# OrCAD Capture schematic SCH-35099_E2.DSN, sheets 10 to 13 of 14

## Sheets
10 10 Pheriperals: size C
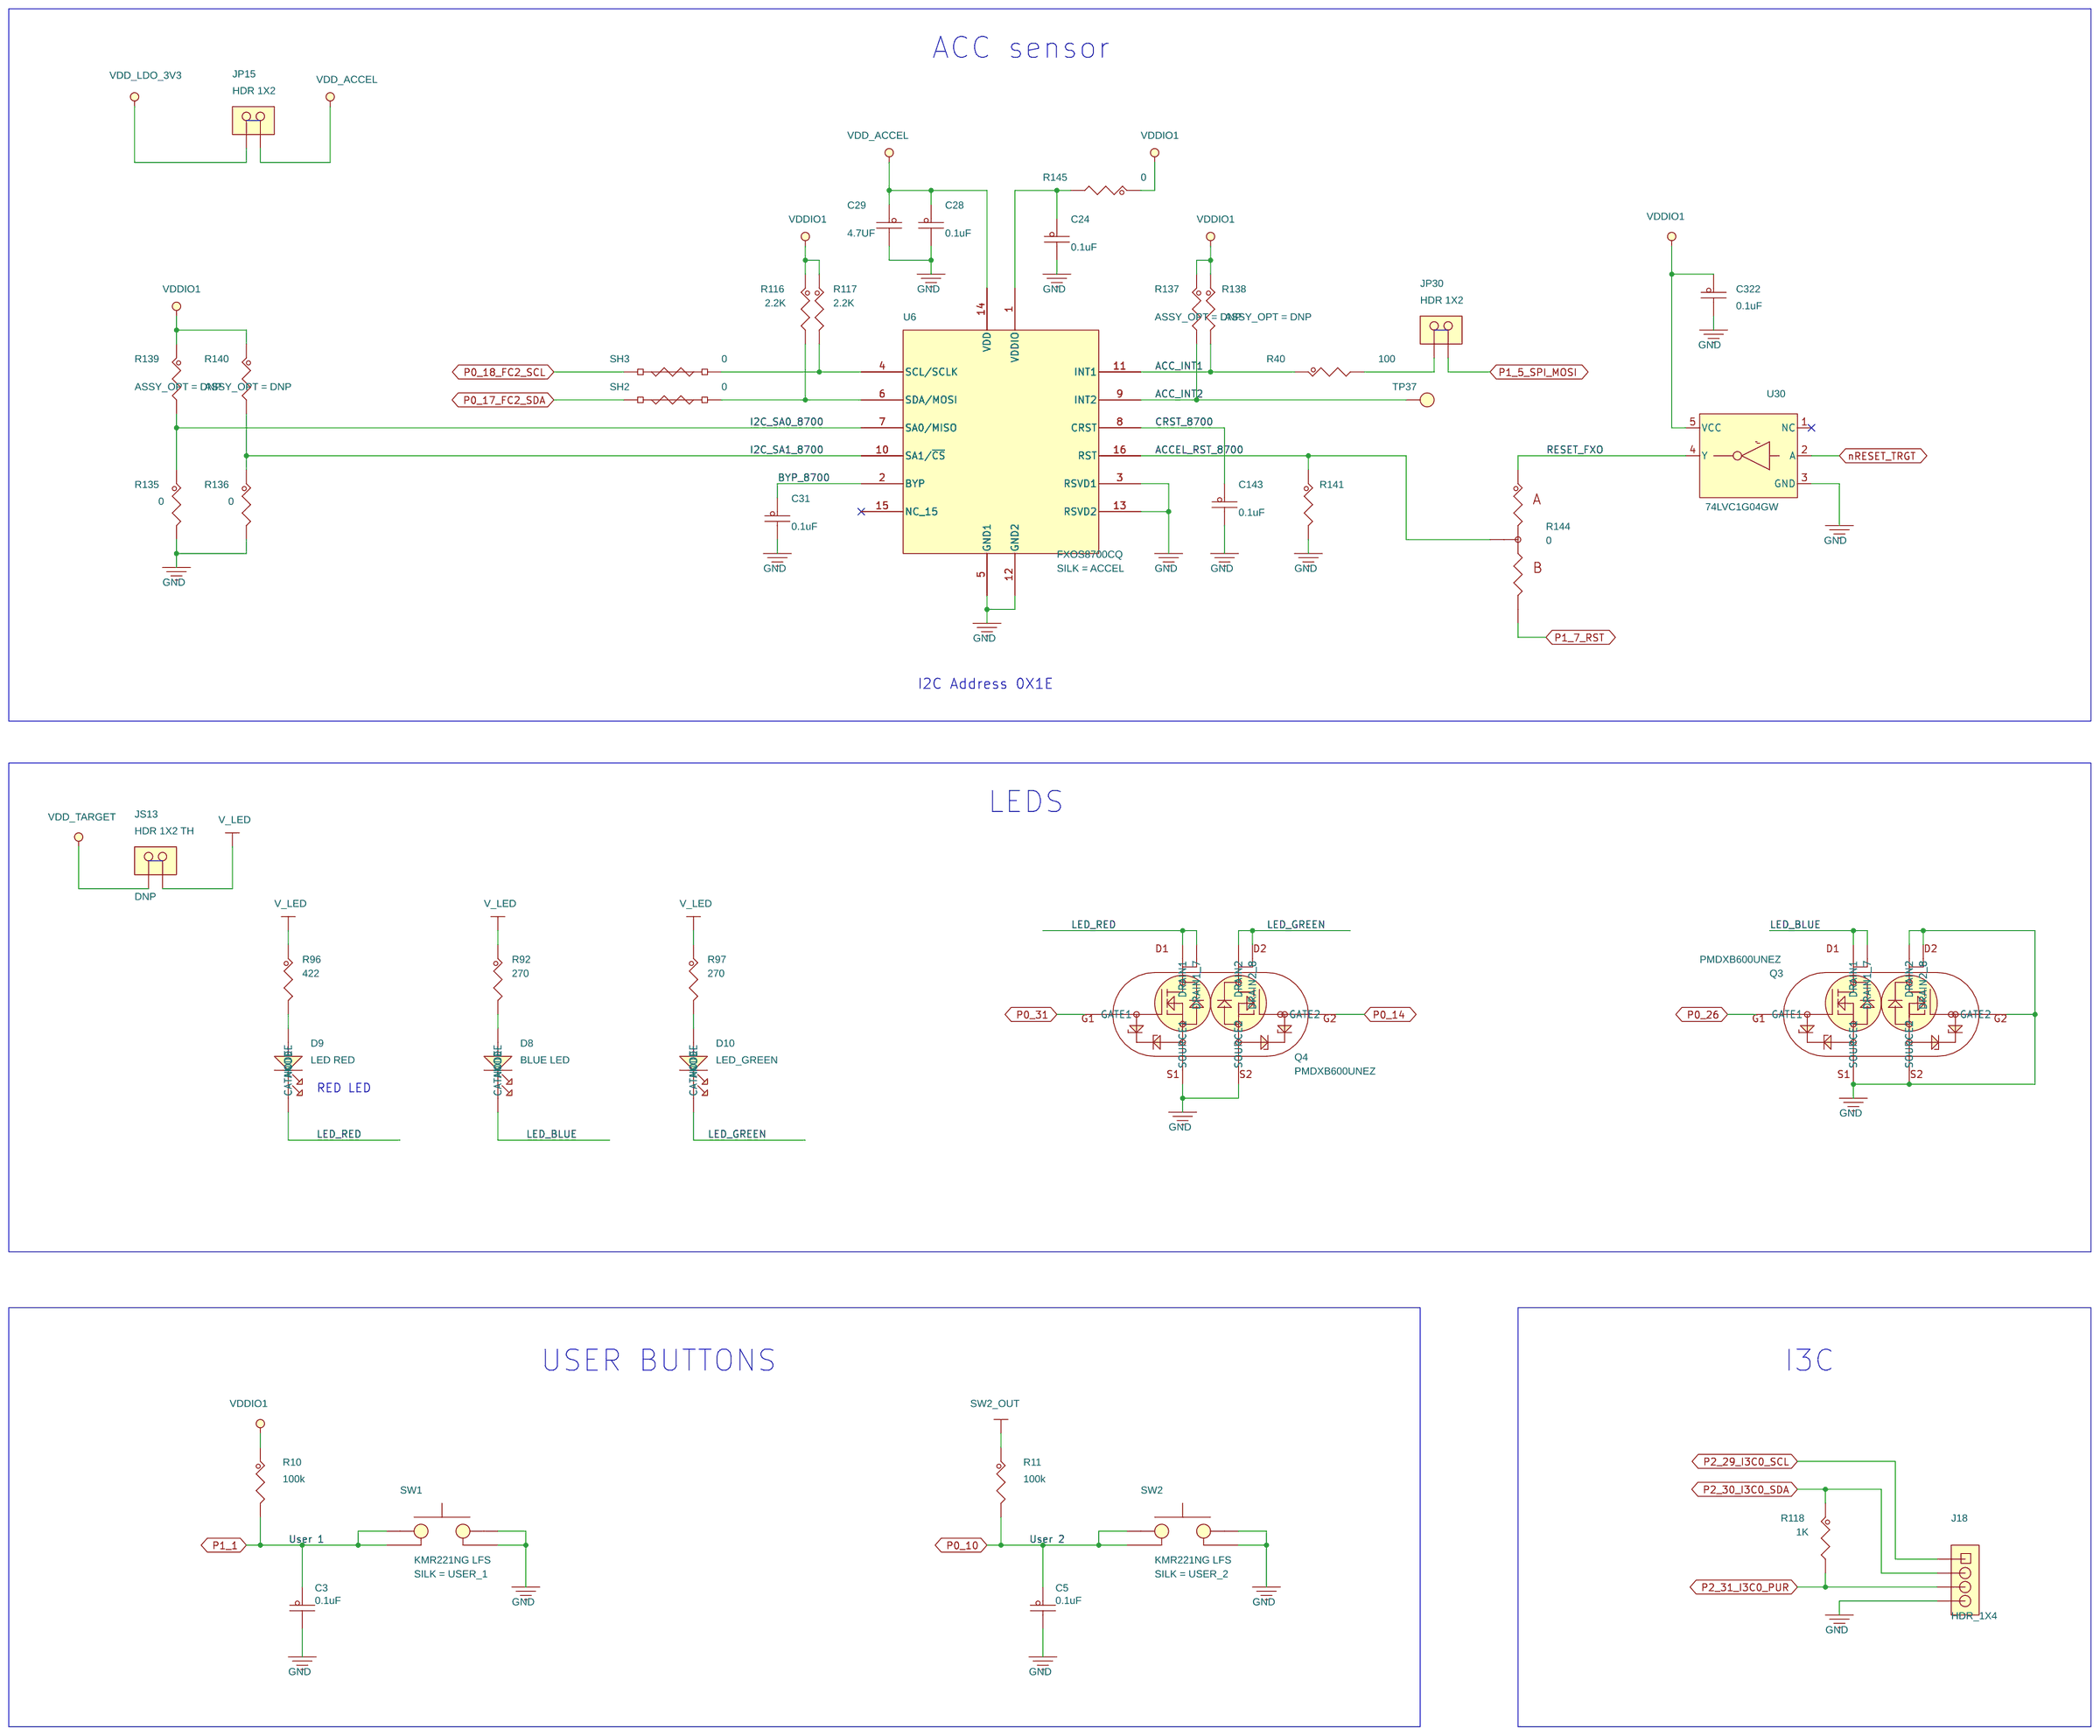
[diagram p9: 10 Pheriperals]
11 13 Debug Translator: size C
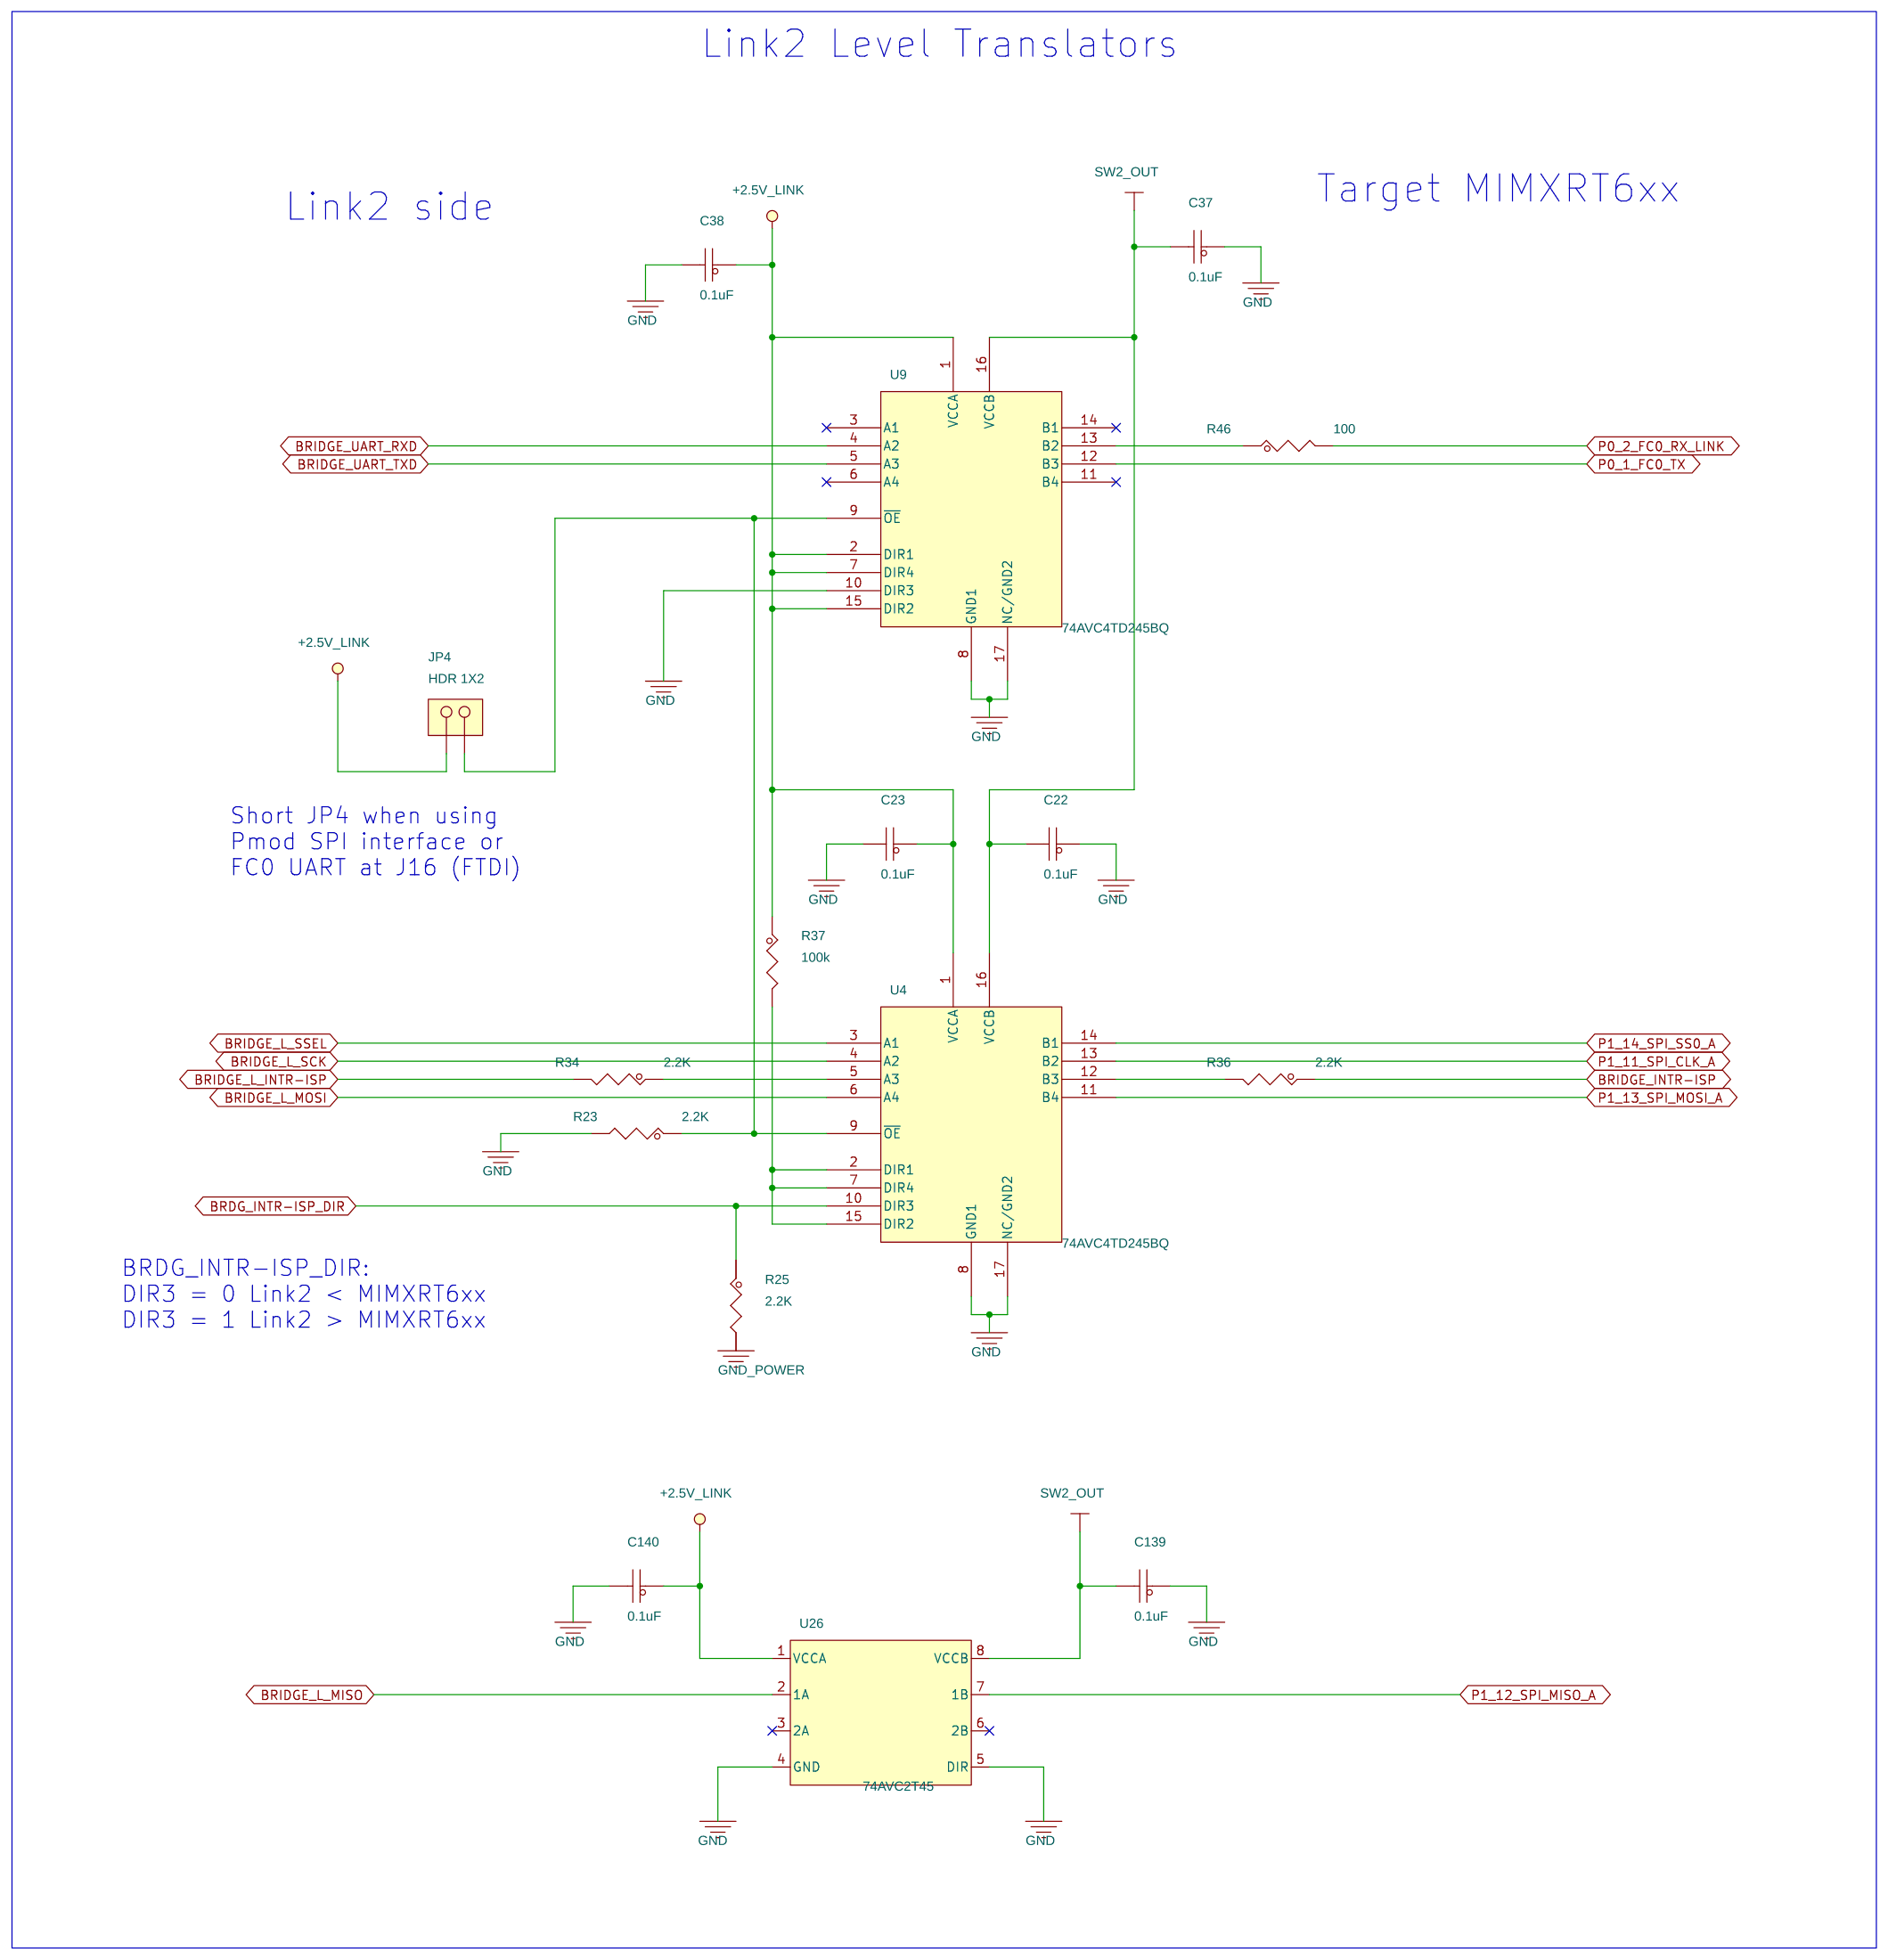
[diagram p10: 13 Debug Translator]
12 14 Link2 Debug: size C
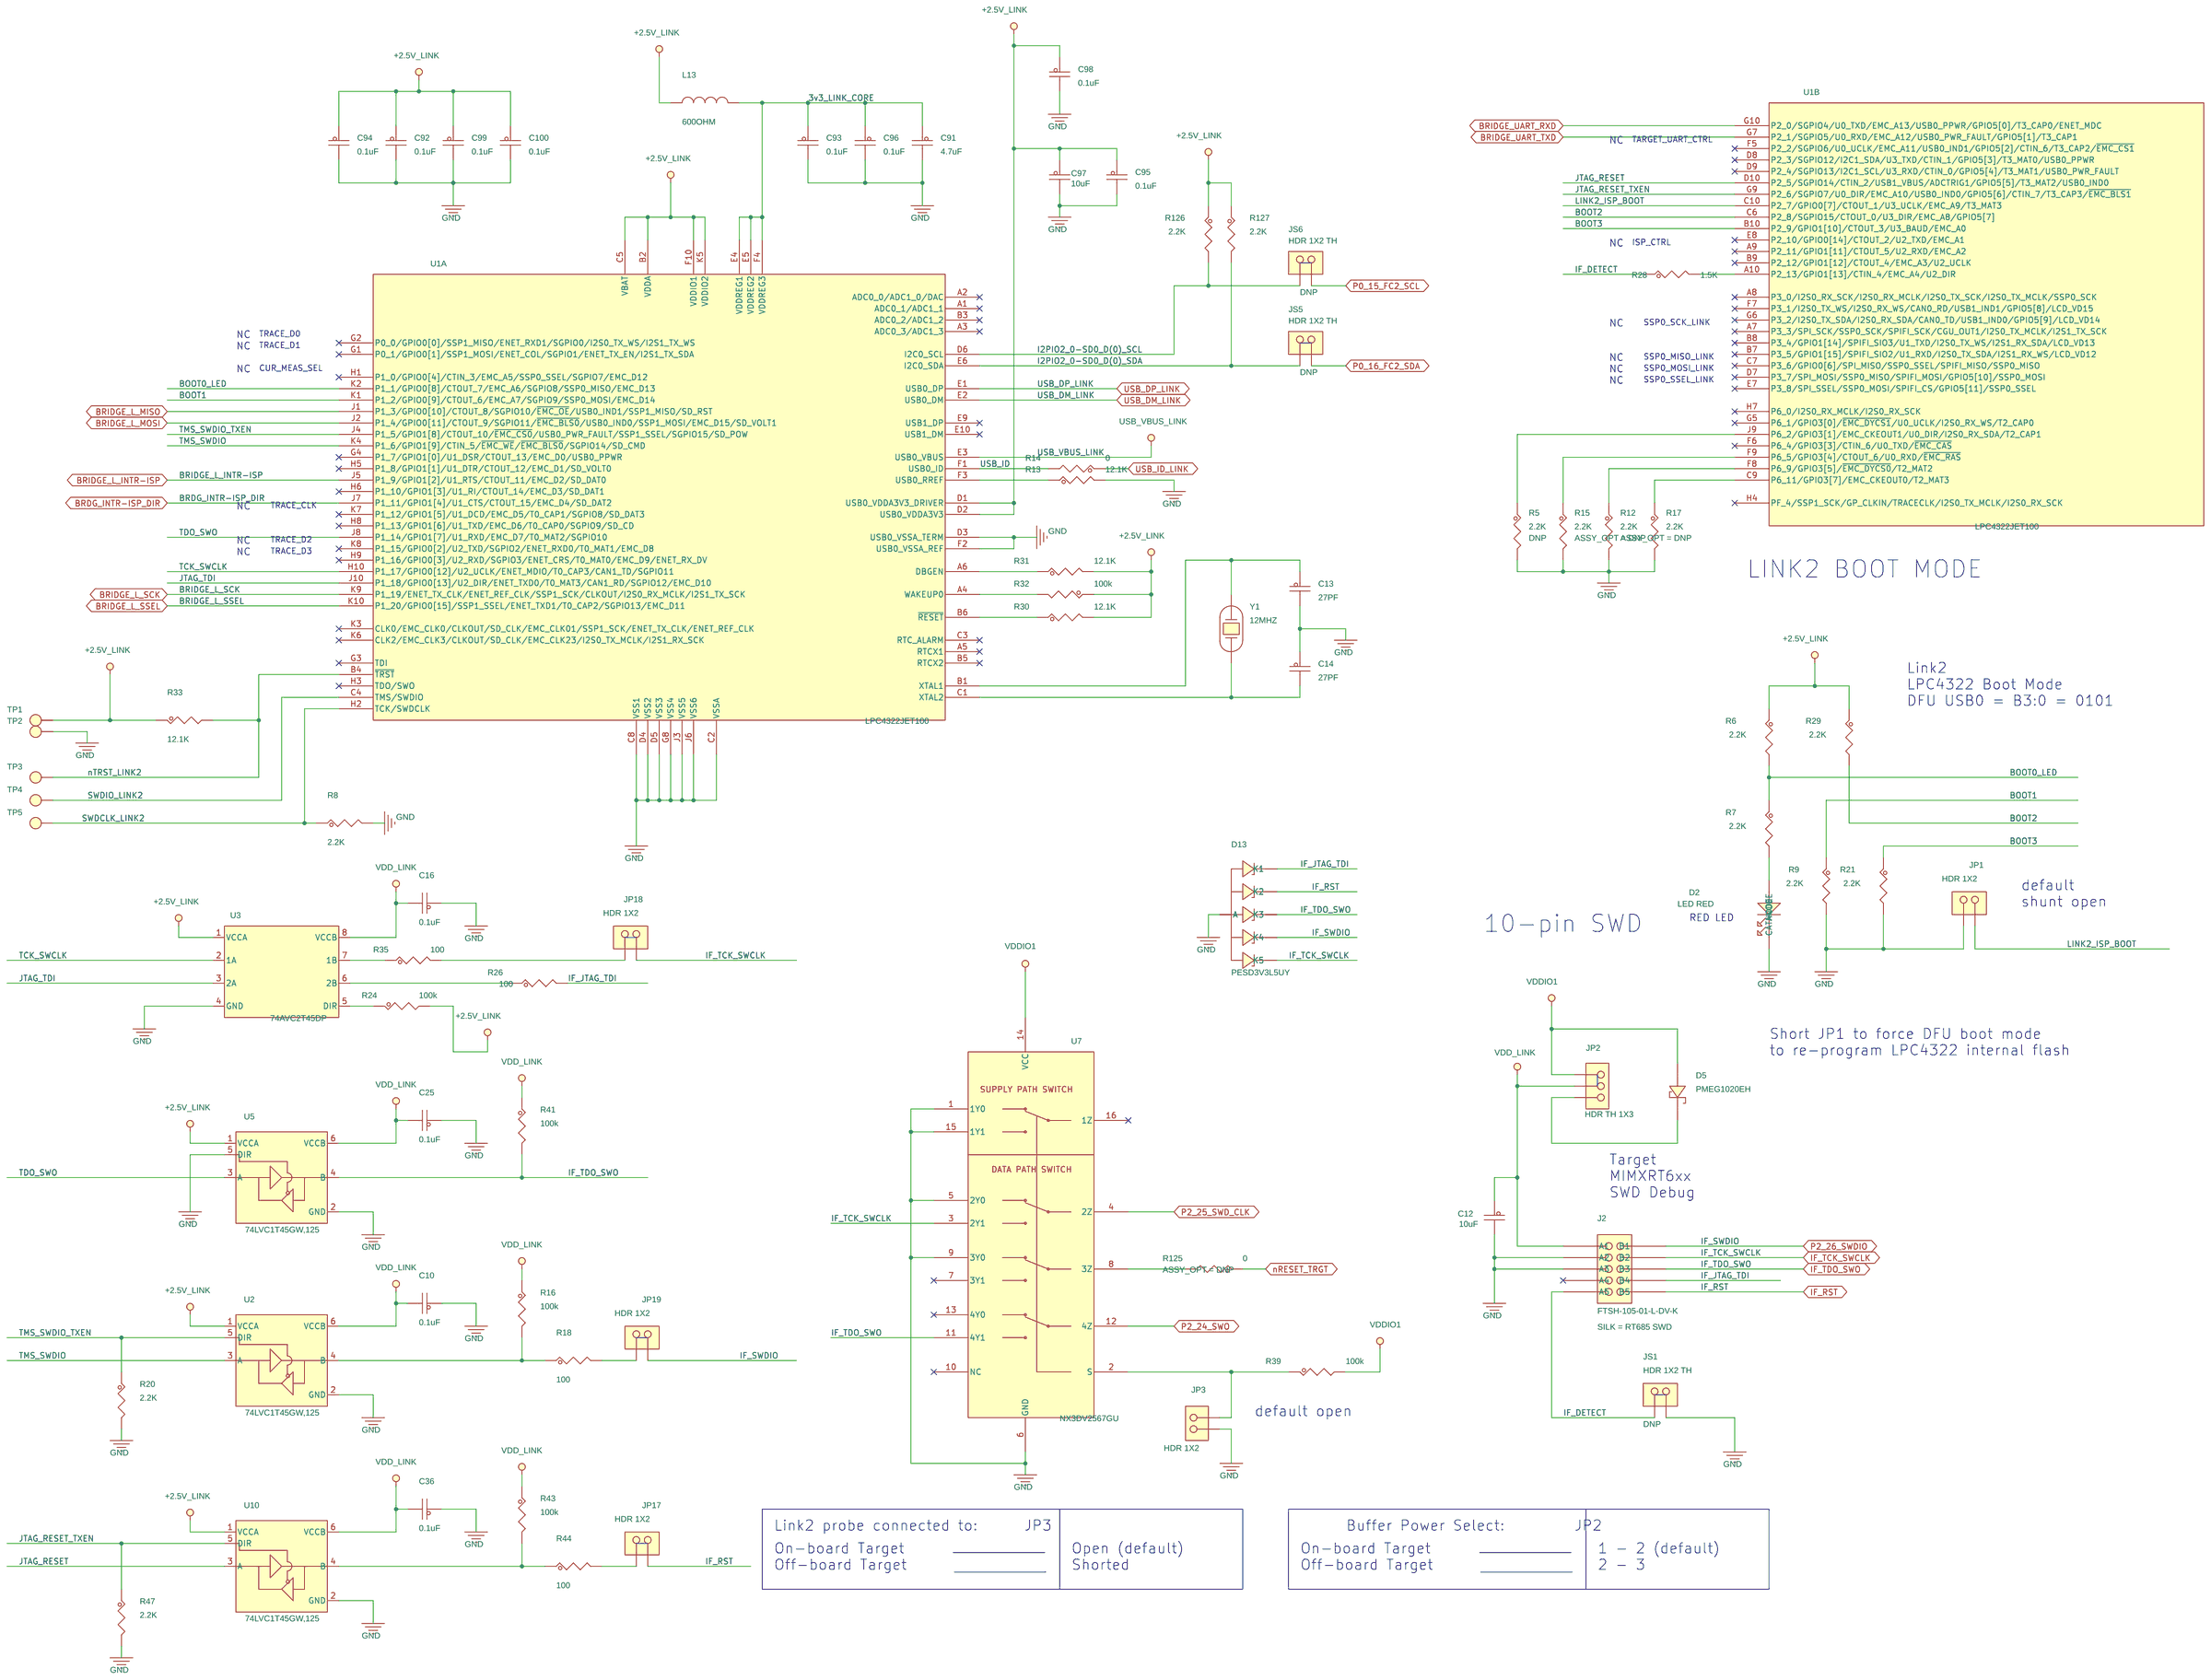
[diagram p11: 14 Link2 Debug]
13 06 Audio Codec/DMIC: size C
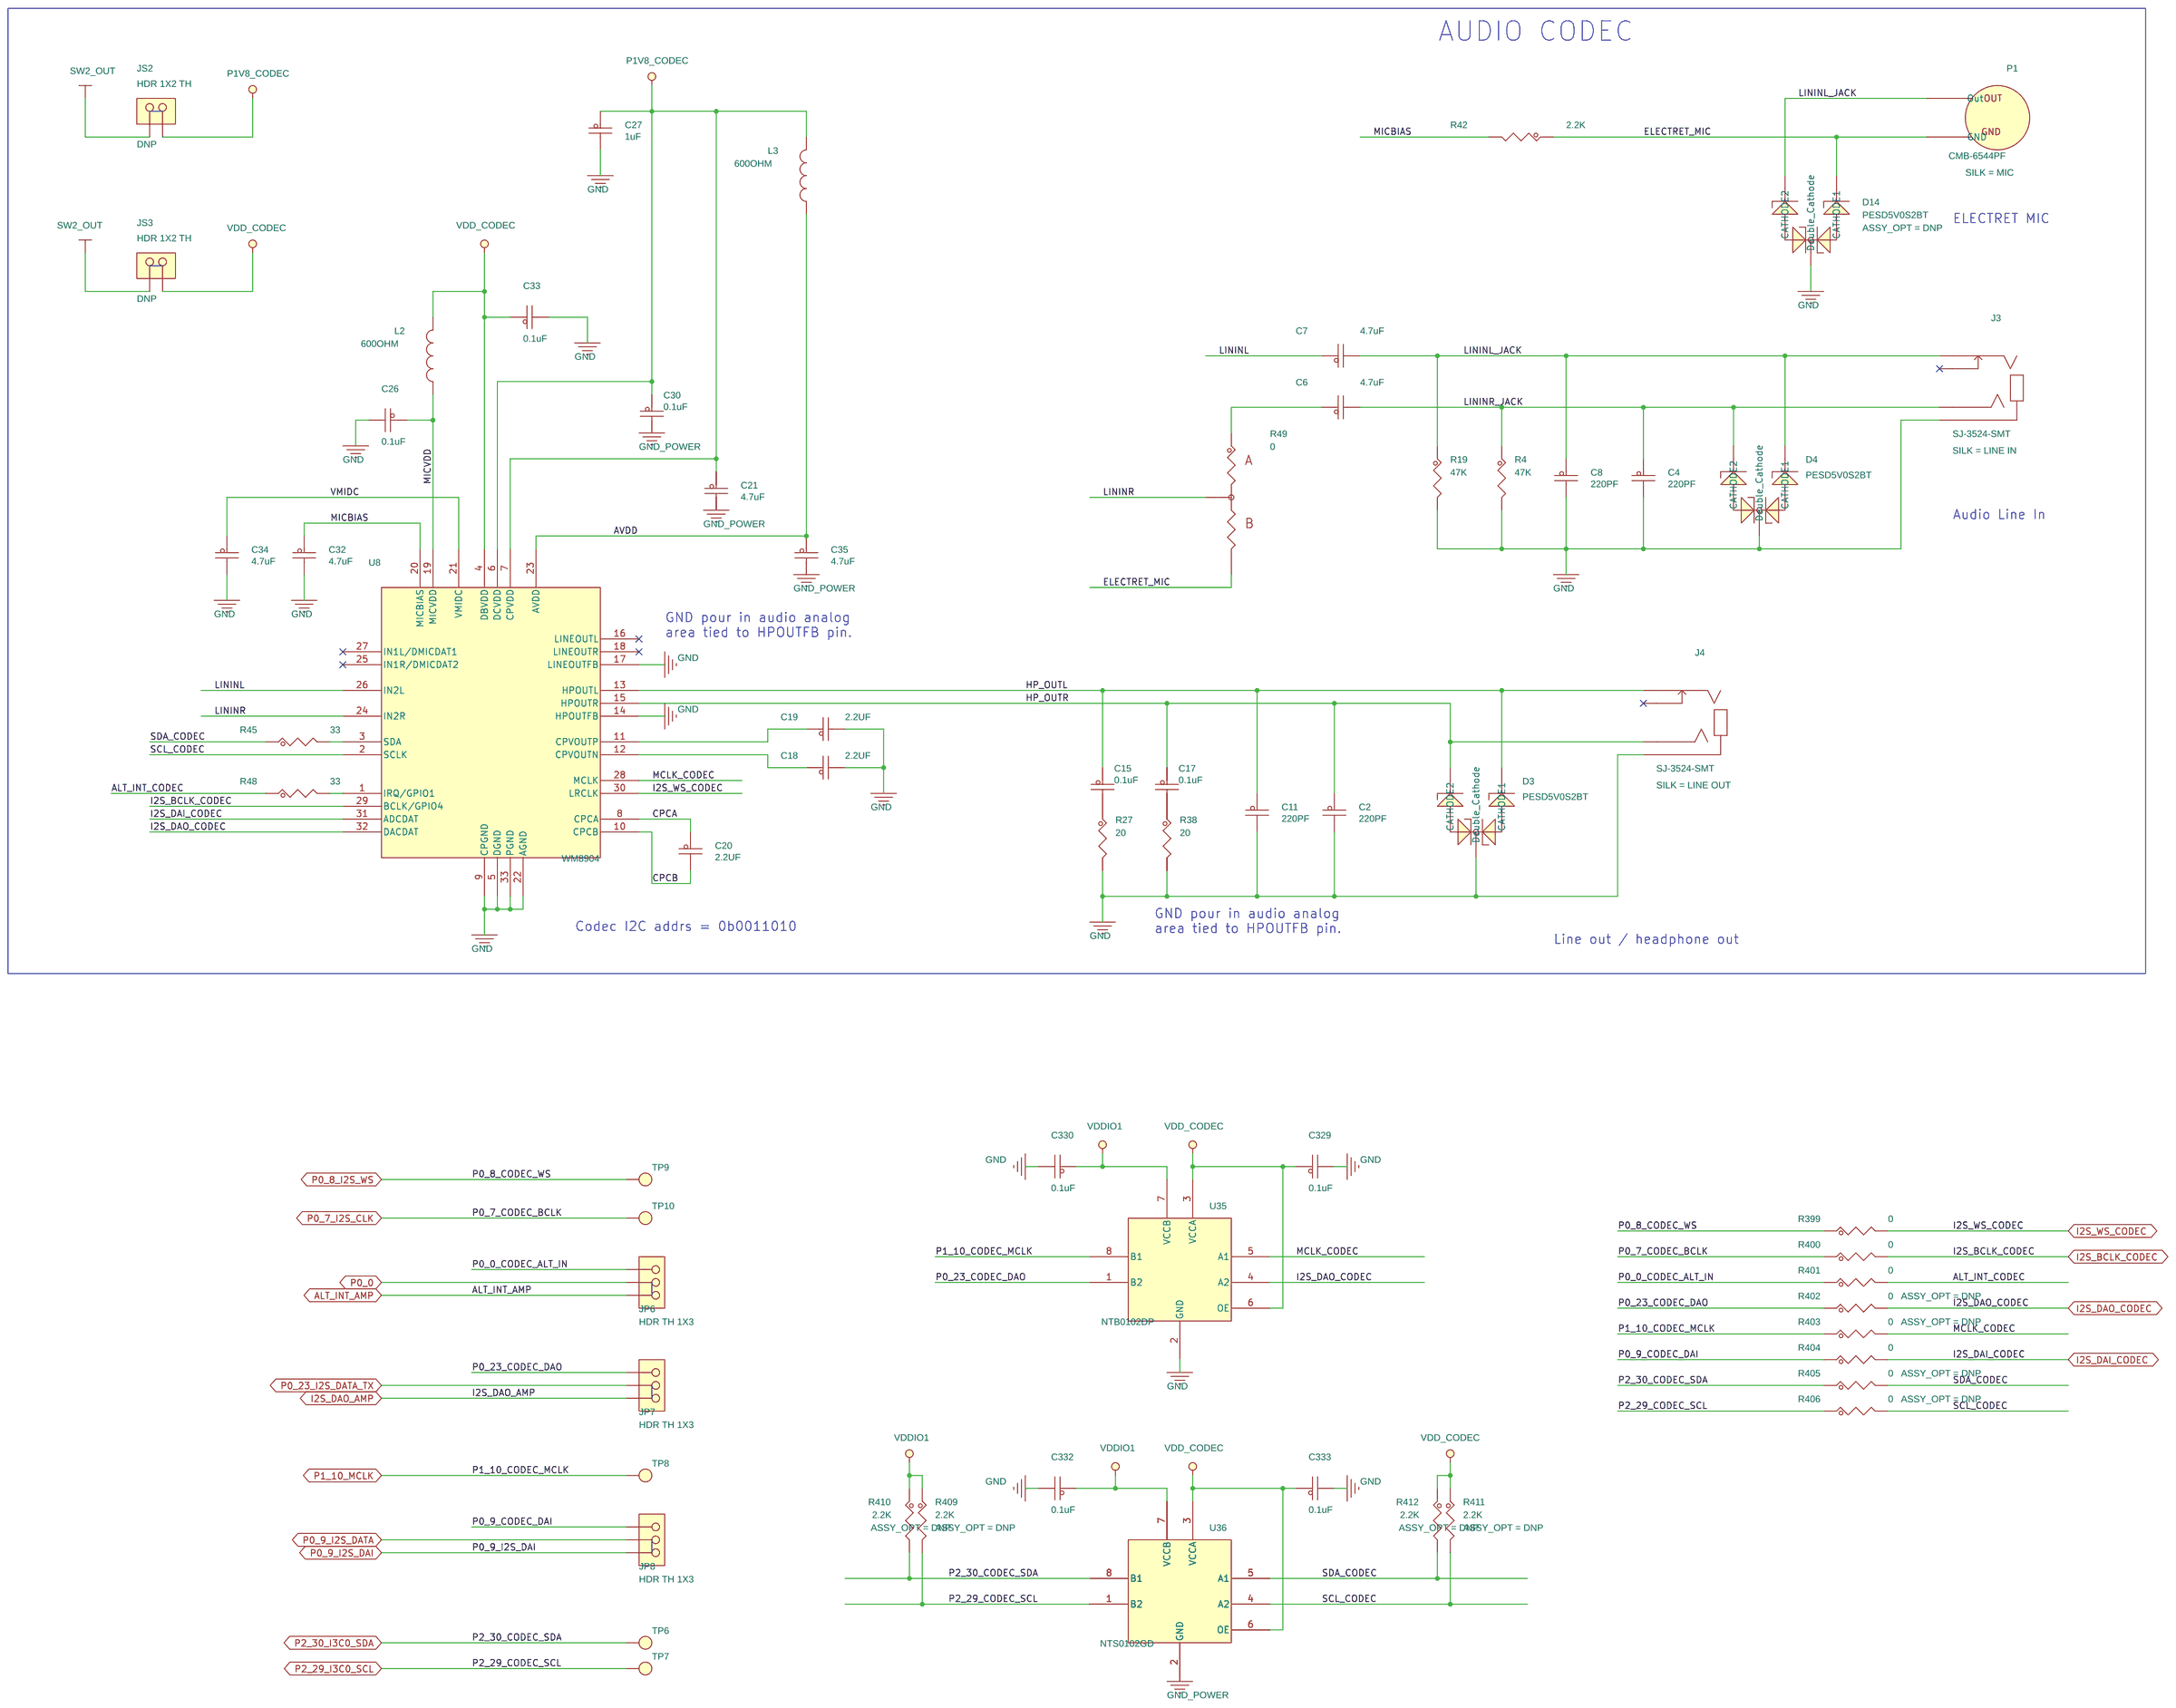
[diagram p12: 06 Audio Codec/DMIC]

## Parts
sheet 06 Audio Codec/DMIC
C2  220PF  [CC0402_25]
C4  220PF  [CC0402_25]
C6  4.7uF  [CC0603_OV]
C7  4.7uF  [CC0603_OV]
C8  220PF  [CC0402_25]
C11  220PF  [CC0402_25]
C15  0.1uF  [CC0402_25]
C17  0.1uF  [CC0402_25]
C18  2.2UF  [CC0402_25]
C19  2.2UF  [CC0402_25]
C20  2.2UF  [CC0402_25]
C21  4.7uF  [CC0603_OV]
C26  0.1uF  [CC0402_25]
C27  1uF  [cc0402_tol0p15_ov]
C30  0.1uF  [CC0402_25]
C32  4.7uF  [CC0603_OV]
C33  0.1uF  [CC0402_25]
C34  4.7uF  [CC0603_OV]
C35  4.7uF  [CC0603_OV]
C329  0.1uF  [CC0402_25]
C330  0.1uF  [CC0402_25]
C332  0.1uF  [CC0402_25]
C333  0.1uF  [CC0402_25]
D3  PESD5V0S2BT  [sot23_a]
D4  PESD5V0S2BT  [sot23_a]
D14  PESD5V0S2BT  [sot23_a]
J3  SJ-3524-SMT  [con4_jack_5x17]
J4  SJ-3524-SMT  [con4_jack_5x17]
JP6  HDR TH 1X3  [HDR103]
JP7  HDR TH 1X3  [HDR103]
JP8  HDR TH 1X3  [HDR103]
JS2  HDR 1X2 TH  [SH_HDR102_BOTTOM]
JS3  HDR 1X2 TH  [SH_HDR102_BOTTOM]
L2  600OHM  [ind_1p8x1mm_sm]
L3  600OHM  [ind_1p8x1mm_sm]
P1  CMB-6544PF  [mic_9mm_th]
R4  47K  [RC0402_25]
R19  47K  [RC0402_25]
R27  20  [RC0402_25]
R38  20  [RC0402_25]
R42  2.2K  [RC0402_25]
R45  33  [RC0402_25]
R48  33  [RC0402_25]
R49  0  [R603-X2]
R399  0  [RC0402_25]
R400  0  [RC0402_25]
R401  0  [RC0402_25]
R402  0  [RC0402_25]
R403  0  [RC0402_25]
R404  0  [RC0402_25]
R405  0  [RC0402_25]
R406  0  [RC0402_25]
R409  2.2K  [RC0402_25]
R410  2.2K  [RC0402_25]
R411  2.2K  [RC0402_25]
R412  2.2K  [RC0402_25]
TP6  TPAD_050  [TPAD_050]
TP7  TPAD_050  [TPAD_050]
TP8  TPAD_050  [TPAD_050]
TP9  TPAD_050  [TPAD_050]
TP10  TPAD_050  [TPAD_050]
U8  WM8904  [qfn32_0p4_4p1sq_2p8ep]
U35  NTB0102DP  [tssop8_a]
U36  NTS0102GD  [xson8_0p5_3p1x2p1]
sheet 10 Pheriperals
C3  0.1uF  [CC0402_25]
C5  0.1uF  [CC0402_25]
C24  0.1uF  [CC0402_25]
C28  0.1uF  [CC0402_25]
C29  4.7UF  [cc0402_tol0p15_ov]
C31  0.1uF  [CC0402_25]
C143  0.1uF  [CC0402_25]
C322  0.1uF  [CC0402_25]
D8  BLUE LED  [LED_0603]
D9  LED RED  [LED_0603]
D10  LED_GREEN  [LED_0603]
J18  HDR_1X4  [JUMP1X4-6040]
JP15  HDR 1X2  [HDR102]
JP30  HDR 1X2  [HDR102]
JS13  HDR 1X2 TH  [SH_HDR102_BOTTOM]
Q3  PMDXB600UNEZ  [dfn1010n-6_0p35_1p15x1p05]
Q4  PMDXB600UNEZ  [dfn1010n-6_0p35_1p15x1p05]
R10  100k  [RC0402_25]
R11  100k  [RC0402_25]
R40  100  [RC0402_25]
R92  270  [RC0402_25]
R96  422  [RC0402_25]
R97  270  [RC0402_25]
R116  2.2K  [RC0402_25]
R117  2.2K  [RC0402_25]
R118  1K  [RC0402_25]
R135  0  [RC0402_25]
R136  0  [RC0402_25]
R137  10K  [0402_CC]
R138  10K  [0402_CC]
R139  10K  [0402_CC]
R140  10K  [0402_CC]
R141  10K  [0402_CC]
R144  0  [R603-X2]
R145  0  [RC0402_25]
SH2  0  [SH0402]
SH3  0  [SH0402]
SW1  KMR221NG LFS  [sw4_4p2x2p8_sm]
SW2  KMR221NG LFS  [sw4_4p2x2p8_sm]
TP37  TPAD_050  [TPAD_050]
U6  FXOS8700CQ  [QFN5X3_0P5_3X3]
U30  74LVC1G04GW  [sc70-5]
sheet 13 Debug Translator
C22  0.1uF  [CC0402_25]
C23  0.1uF  [CC0402_25]
C37  0.1uF  [CC0402_25]
C38  0.1uF  [CC0402_25]
C139  0.1uF  [CC0402_25]
C140  0.1uF  [CC0402_25]
JP4  HDR 1X2  [HDR102]
R23  2.2K  [RC0402_25]
R25  2.2K  [RC0402_25]
R34  2.2K  [RC0402_25]
R36  2.2K  [RC0402_25]
R37  100k  [RC0402_25]
R46  100  [RC0402_25]
U4  74AVC4TD245BQ  [dhvqfn16_0p5_3p6x2p6]
U9  74AVC4TD245BQ  [dhvqfn16_0p5_3p6x2p6]
U26  74AVC2T45  [ssop8_dcu]
sheet 14 Link2 Debug
C10  0.1uF  [CC0402_25]
C12  10uF  [CC0603_OV]
C13  27PF  [CC0402_25]
C14  27PF  [CC0402_25]
C16  0.1uF  [CC0402_25]
C25  0.1uF  [CC0402_25]
C36  0.1uF  [CC0402_25]
C91  4.7uF  [CC0603_OV]
C92  0.1uF  [CC0402_25]
C93  0.1uF  [CC0402_25]
C94  0.1uF  [CC0402_25]
C95  0.1uF  [CC0402_25]
C96  0.1uF  [CC0402_25]
C97  10uF  [CC0603_OV]
C98  0.1uF  [CC0402_25]
C99  0.1uF  [CC0402_25]
C100  0.1uF  [CC0402_25]
D2  LED RED  [LED_0603]
D5  PMEG1020EH  [SOD123LF]
D13  PESD3V3L5UY  [sot-363_0p65_smt]
J2  FTSH-105-01-L-DV-K  [hdr205_10m_50_sm_k]
JP1  HDR 1X2  [HDR102]
JP2  HDR TH 1X3  [HDR103]
JP3  HDR 1X2  [HDR102]
JP17  HDR 1X2  [HDR102]
JP18  HDR 1X2  [HDR102]
JP19  HDR 1X2  [HDR102]
JS1  HDR 1X2 TH  [SH_HDR102_BOTTOM]
JS5  HDR 1X2 TH  [SH_HDR102_BOTTOM]
JS6  HDR 1X2 TH  [SH_HDR102_BOTTOM]
L13  600OHM  [ind_1p8x1mm_sm]
R5  2.2K  [RC0402_25]
R6  2.2K  [RC0402_25]
R7  2.2K  [RC0402_25]
R8  2.2K  [RC0402_25]
R9  2.2K  [RC0402_25]
R12  2.2K  [RC0402_25]
R13  12.1K  [RC0402_25]
R14  0  [RC0402_25]
R15  2.2K  [RC0402_25]
R16  100k  [RC0402_25]
R17  2.2K  [RC0402_25]
R18  100  [RC0402_25]
R20  2.2K  [RC0402_25]
R21  2.2K  [RC0402_25]
R24  100k  [RC0402_25]
R26  100  [RC0402_25]
R28  1.5K  [RC0402_25]
R29  2.2K  [RC0402_25]
R30  12.1K  [RC0402_25]
R31  12.1K  [RC0402_25]
R32  100k  [RC0402_25]
R33  12.1K  [RC0402_25]
R35  100  [RC0402_25]
R39  100k  [RC0402_25]
R41  100k  [RC0402_25]
R43  100k  [RC0402_25]
R44  100  [RC0402_25]
R47  2.2K  [RC0402_25]
R125  0  [RC0402_25]
R126  2.2K  [RC0402_25]
R127  2.2K  [RC0402_25]
TP1  TPAD_050  [TPAD_050]
TP2  TPAD_050  [TPAD_050]
TP3  TPAD_050  [TPAD_050]
TP4  TPAD_050  [TPAD_050]
TP5  TPAD_050  [TPAD_050]
U1  LPC4322JET100  [fbga100_0p8_9x9]  (sections A,B)
U2  74LVC1T45GW,125  [SOT-363_0P65_SMT]
U3  74AVC2T45DP  [msop_8p_0p65_3x3mm]
U5  74LVC1T45GW,125  [SOT-363_0P65_SMT]
U7  NX3DV2567GU  [pqfn16_0p4_2p65x1p85]
U10  74LVC1T45GW,125  [SOT-363_0P65_SMT]
Y1  12MHZ  [xtl2_11p6x4p85_sm]

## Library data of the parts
C2 C4 C8 C11 = CAP_NP: CAP CER 220PF 50V 5% C0G 0402; AGILE_PN: 150-30297; CAD_APPROVED: Yes; FPLIST: CC0402_25,CC0402_HD,0402_CC; HEIGHT: 0.55MM; MFG_NAME01: KEMET; MFG_PN01: C0402C221J5GAC; Package Size: 0402; ROHS: Yes; Tolerance: 5%; VOLTAGE: 50V
C6 C7 C21 C32 C34 C35 C91 = CAP_NP: CAP CER 4.7UF 10V 10% X5R 0603; AGILE_PN: 150-77975; CAD_APPROVED: Yes; FPLIST: CC0603_OV,CC0603,0603_CC; HEIGHT: 0.9MM; MFG_NAME01: TAIYO YUDEN; MFG_PN01: LMK107BJ475KA-T; Package Size: 0603; Package Type: tape & reel; ROHS: Yes; Tolerance: 10%; VOLTAGE: 10V
C3 C5 C10 C15-C17 C22-C26 C28 C30 C31 C33 C36-C38 C92-C96 C98-C100 C139 C140 C143 C322 C329 C330 C332 C333 = CAP_NP: CAP CER 0.1UF 25V 20% X5R 0402; AGILE_PN: 150-80403; CAD_APPROVED: Yes; FPLIST: CC0402_25,CC0402_HD,0402_CC; HEIGHT: 0.55MM; MFG_NAME01: WURTH ELEKTRONIK EISOS GMBH & CO. KG (ELECTRONIC & ELECTROMEHANICAL COMP); MFG_PN01: 885012105018; ROHS: Yes; Temp Range: -55°C to +85°C; Temp_Range: -55°C to +125°C; VOLTAGE: 25V
C18-C20 = CAP_NP: CAP CER 2.2UF 10V 20% X5R 0402; AGILE_PN: 150-79665; CAD_APPROVED: Yes; FPLIST: CC0402_25,CC0402_HD,0402_CC; HEIGHT: 0.55 MM; MFG_NAME01: MURATA; MFG_PN01: GRM155R61A225ME01D; ROHS: Yes; Tolerance: 20%; VOLTAGE: 10V
C27 = CAP_NP: CAP CER 1uF 10V 20% X6S 0402; AGILE_PN: 150-80349; CAD_APPROVED: Yes; FPLIST: CC0402_25,CC0402_HD,0402_CC; HEIGHT: 0.33 MM; MFG_NAME01: TDK; MFG_PN01: CGB2A1X6S1A105M033BC; Package Size: 0402; ROHS: Yes; Temp Range: -55 to +105°C; Tolerance: +/-20%; VOLTAGE: 10V
D3 D4 = DIODE_TVS_C1C2A3: DIODE TVS 5VWM 14VC SOT23; AGILE_PN: 480-79839; CAD_APPROVED: Yes; HEIGHT: 1.1MM; MFG_NAME01: NEXPERIA; MFG_PN01: PESD5V0S2BT,215; REQUESTED_COMPLETION_DATE: Not an expedite request; ROHS: Yes
D14 = DIODE_TVS_C1C2A3: DIODE TVS 5VWM 14VC SOT23; AGILE_PN: 480-79839; ASSY_OPT: DNP; CAD_APPROVED: Yes; HEIGHT: 1.1MM; MFG_NAME01: NEXPERIA; MFG_PN01: PESD5V0S2BT,215; REQUESTED_COMPLETION_DATE: Not an expedite request; ROHS: Yes
J3 = SJ-3524-SMT_4P: CON 4 AUD JACK 3.5MM SMT -- 211H AG; AGILE_PN: 211-79155; CAD_APPROVED: Yes; HEIGHT: 5.37MM; MFG_NAME01: CUI Inc; ROHS: Yes; SILK: LINE IN
J4 = SJ-3524-SMT_4P: CON 4 AUD JACK 3.5MM SMT -- 211H AG; AGILE_PN: 211-79155; CAD_APPROVED: Yes; HEIGHT: 5.37MM; MFG_NAME01: CUI Inc; ROHS: Yes; SILK: LINE OUT
JP2 JP6-JP8 = CONN_HDR_3X1: HDR 1X3 TH 100MIL SP 339H AU 100L; AGILE_PN: 210-75726; CAD_APPROVED: Yes; HEIGHT: 8.65MM; MFG_NAME01: SAMTEC; MFG_PN01: TSW-103-07-G-S; Package Size: 7.62 x 2.54 mm; ROHS: Yes; Temp Range: -55°C to +125°C; Temp_Range: -55°C to +125°C; VOLTAGE: 450 - 550 VAC
JS1-JS3 JS5 JS6 JS13 = CONN_HDR_2X1: HDR 1X2 TH 100MIL SP 339H AU 98L; AGILE_PN: 210-75439; ASSY_OPT: DNP; CAD_APPROVED: YES; FPLIST: HDR102,SH_HDR102_BOTTOM; HEIGHT: 8.71 MM; MFG_NAME01: SAMTEC; MFG_PN01: TSW-102-07-G-S; ROHS: Yes; Temp Range: -55°C to +125°C; Temp_Range: -55°C to +125°C
L2 L3 L13 = INDUCTOR: IND FER BEAD 600OHM@100MHz 1A 25% 0603; AGILE_PN: 180-78469; CAD_APPROVED: Yes; HEIGHT: 1MM; MFG_NAME01: WURTH ELEKTRONIK EISOS GMBH & CO. KG (ELECTRONIC & ELECTROMEHANICAL COMP); MFG_PN01: 742792651; PART_TYPE: FERRITE\BEAD; ROHS: Yes; Tolerance: +/-25%
P1 = MIC: AUDIO DEVICE MIC ELECTRET 20-20000HZ 4.5VDC 9.4MM TH; AGILE_PN: 510-77878; CAD_APPROVED: Yes; HEIGHT: 6.95MM; MFG_NAME01: CUI INC; ROHS: Yes; VOLTAGE: 4.5-10VDC
R4 R19 = RES: RES MF 47K  1/16W 1% 0402; AGILE_PN: 470-31023; CAD_APPROVED: Yes; FPLIST: RC0402_25,RC0402_HD,0402_CC; HEIGHT: 0.40 MM; MFG_NAME01: YAGEO AMERICA; MFG_PN01: RC0402FR-0747KL; ROHS: Yes; Temp Range: –55 °C to +155 °C; Temp_Range: –55 °C to +155 °C; Tolerance: 1%
R27 R38 = RES: RES MF 20 OHM 1/16W 5% 0402; AGILE_PN: 470-75603; CAD_APPROVED: Yes; FPLIST: RC0402_25,RC0402_HD,0402_CC; HEIGHT: 0.4 MM; MFG_NAME01: BOURNS; MFG_PN01: CR0402-JW-200GLF; ROHS: Yes; Tolerance: 5%
R6-R9 R17 R20 R21 R23 R25 R29 R34 R36 R42 R47 R116 R117 R126 R127 = RES: RES MF 2.2K 1/16W 5% 0402; AGILE_PN: 470-76602; CAD_APPROVED: Yes; FPLIST: RC0402_25,RC0402_HD,0402_CC; HEIGHT: 0.4 MM; MFG_NAME01: YAGEO AMERICA; MFG_PN01: RC0402JR-072K2L; ROHS: Yes; Temp_Range: -55C to +155C; Tolerance: 5%
R45 R48 = RES: RES MF 33.0 OHM 1/16W 5% 0402; AGILE_PN: 470-81889; CAD_APPROVED: Yes; FPLIST: RC0402_25,RC0402_HD,0402_CC; HEIGHT: 0.4MM; MFG_NAME01: YAGEO; MFG_PN01: RC0402JR-0733RL; ROHS: Yes; Temp Range: -55C to +155C; Tolerance: 5%; VOLTAGE: 50V
R49 R144 = RES_0603_X2: RES MF ZERO OHM 1/10W -- 0603; AGILE_PN: 470-80866; CAD_APPROVED: Yes; FPLIST: RC0603_OV,RC0603,R603-X2,0603_CC,IND_0603HP_NSP,CC0603_OV_NSP; HEIGHT: 0.6MM; MFG_NAME01: YAGEO AMERICA; MFG_PN01: RC0603FR-070RL; ROHS: Yes; Temp Range: –55 °C to +155 °C; Temp_Range: –55 °C to +155 °C
R399-R401 R404 = RES: RES MF ZERO OHM 1/16W -- AEC-Q200 0402; AGILE_PN: 470-81849; CAD_APPROVED: Yes; FPLIST: RC0402_25,RC0402_HD,0402_CC; HEIGHT: 0.45 MM; MFG_NAME01: STACKPOLE ELECTRONICS; MFG_PN01: RMCF0402ZT0R00; ROHS: Yes
R402 R403 R405 R406 = RES: RES MF ZERO OHM 1/16W -- AEC-Q200 0402; AGILE_PN: 470-81849; ASSY_OPT: DNP; CAD_APPROVED: Yes; FPLIST: RC0402_25,RC0402_HD,0402_CC; HEIGHT: 0.45 MM; MFG_NAME01: STACKPOLE ELECTRONICS; MFG_PN01: RMCF0402ZT0R00; ROHS: Yes
R5 R12 R15 R409-R412 = RES: RES MF 2.2K 1/16W 5% 0402; AGILE_PN: 470-76602; ASSY_OPT: DNP; CAD_APPROVED: Yes; FPLIST: RC0402_25,RC0402_HD,0402_CC; HEIGHT: 0.4 MM; MFG_NAME01: YAGEO AMERICA; MFG_PN01: RC0402JR-072K2L; ROHS: Yes; Temp_Range: -55C to +155C; Tolerance: 5%
TP1-TP10 TP37 = TEST_POINT_L: TEST POINT PAD 50MIL DIA SMT, NO PART TO ORDER; AGILE_PN: 211-76644; CAD_APPROVED: Yes; EN: 666-1-00186; HEIGHT: 0.1MM; KEY Number: 666-1-00186@1; MFG_NAME01: NOTACOMPONENT; MFG_PN01: NOTACOMPONENT; Mfg: NA; Mfg Part No: 666-1-00186; ROHS: Yes
U8 = WM8904CGEFL_QFN32: IC AUDIO ULTRA LOW POWER CODEC 1V QFN32; AGILE_PN: 315-81538; CAD_APPROVED: Yes; HEIGHT: 0.8MM; MFG_NAME01: CIRRUS LOGIC; MFG_PN01: WM8904CGEFL/V; ROHS: Yes; Temp Range: -40C to +85C; Temp_Range: -40C to +85C; VOLTAGE: -0.3 - 4.5V
U35 = NTB0102DP: IC DUAL VXLTR XCVR 2BIT 1.2-3.6/1.65-5.5V TSSOP8; AGILE_PN: 312-81226; CAD_APPROVED: Yes; HEIGHT: 1.1MM; MFG_NAME01: NXP SEMICONDUCTORS; MFG_PN01: NTB0102DP,125; ROHS: Yes; VOLTAGE: 1.2-3.6V/1.65-5.5V
U36 = NTS0102: IC DUAL SUPPLY XCVR 50 MBPS 1.65-3.6V/2.3-5.5V XSON8; AGILE_PN: 312-82318; CAD_APPROVED: Yes; HEIGHT: 0.5MM; MFG_NAME01: NXP SEMICONDUCTORS; MFG_PN01: NTS0102GD,125; ROHS: Yes; Temp Range: -40°C to +125°C; VOLTAGE: 1.65-3.6V/2.3-5.5V
C29 = CAP_NP: CAP CER 4.7uF 10V 20% X5R 0402_WIDE; AGILE_PN: 150-79667; CAD_APPROVED: Yes; FPLIST: CC0402_25,CC0402_HD,0402_CC; HEIGHT: 0.7 MM; MFG_NAME01: MURATA; MFG_PN01: GRM155R61A475MEAA; Package Size: 0402; ROHS: Yes; Temp Range: -55 to 85; Temp_Range: -55 to 85; Tolerance: 20%; VOLTAGE: 10V
D8 = LED: LED BLUE CLEAR SGL 20MA 3.2V 0603 SMT; AGILE_PN: 370-76775; CAD_APPROVED: Yes; HEIGHT: 0.8MM; MFG_NAME01: WURTH ELEKTRONIK EISOS GMBH & CO. KG (ELECTRONIC & ELECTROMEHANICAL COMP); MFG_PN01: 150060BS75000; REQUESTED_COMPLETION_DATE: Not an expedite request; ROHS: Yes; Temp Range: -40°C to 85°C; VOLTAGE: 3.2V
D2 D9 = LED: LED BRIGHT RED CLEAR SGL 2V 20MA SMT 0603; AGILE_PN: 370-76779; CAD_APPROVED: Yes; HEIGHT: 0.80MM; MFG_NAME01: WURTH ELEKTRONIK EISOS GMBH & CO. KG (ELECTRONIC & ELECTROMEHANICAL COMP); MFG_PN01: 150060RS75000; REQUESTED_COMPLETION_DATE: Not an expedite request; ROHS: Yes; VOLTAGE: 2V
D10 = LED: LED ULTRA-BRIGHT GREEN SMT 0603; AGILE_PN: 370-75077; CAD_APPROVED: YES; HEIGHT: 0.8MM; MFG_NAME01: LITE ON; MFG_PN01: LTST-C190KGKT; ROHS: Yes; Rated Voltage: 2V; VOLTAGE: 2V
J18 = HDR-1X4: HDR 1X4 TH 100MIL SP  336H AU 100L; AGILE_PN: 210-75688; CAD_APPROVED: Yes; HEIGHT: 8.4mm; MFG_NAME01: SAMTEC; MFG_PN01: TSW-104-07-G-S; ROHS: Yes; VOLTAGE: 450 - 550 VAC
JP1 JP3 JP4 JP15 JP17-JP19 JP30 = CONN_HDR_2X1: HDR 1X2 TH 100MIL SP 338H SN 100L; AGILE_PN: 210-80102; CAD_APPROVED: Yes; HEIGHT: 8.58MM; MFG_NAME01: SAMTEC; MFG_PN01: TSW-102-07-T-S; Package Size: 5.08 x 2.54 mm; ROHS: Yes
Q3 Q4 = NMOS_DUAL_PMDXB600UNE_8P: TRAN NMOS PWR SW 600mA 20V 620mOHM DFN1010B-6; AGILE_PN: 480-79619; CAD_APPROVED: Yes; HEIGHT: 0.4MM; MFG_NAME01: NEXPERIA; ROHS: Yes; VOLTAGE: 20V
R10 R11 R16 R24 R32 R37 R39 R41 R43 = RES: RES MF 100K 1/16W 5% 100ppm/C 0402; AGILE_PN: 470-82058; CAD_APPROVED: Yes; FPLIST: RC0402_25,RC0402_HD,0402_CC; HEIGHT: 0.40 MM; MFG_NAME01: YAGEO AMERICA; MFG_PN01: RC0402JR-07100KL; ROHS: Yes; Temp Range: -55C to +155C; Tolerance: 5%; VOLTAGE: 50V
R18 R26 R35 R40 R44 R46 = RES: RES MF 100 OHM 1/16W 5% 0402; AGILE_PN: 470-82143; CAD_APPROVED: Yes; FPLIST: RC0402_25,RC0402_HD,RC0402_X2,0402_CC; HEIGHT: 0.45MM; MFG_NAME01: YAGEO AMERICA; MFG_PN01: RC0402JR-07100RL; ROHS: Yes; Temp Range: -55°C to +155°C; Tolerance: 5%
R92 R97 = RES: RES MF 270 OHM 1/16W 5% 0402; AGILE_PN: 470-81890; CAD_APPROVED: Yes; FPLIST: RC0402_25,RC0402_HD,0402_CC; HEIGHT: 0.4MM; MFG_NAME01: YAGEO; MFG_PN01: RC0402JR-07270RL; ROHS: Yes; Temp Range: -55C to +155C; Tolerance: 5%
R96 = RES: RES MF 422 OHM 1/16W 1% 0402; AGILE_PN: 470-30800; CAD_APPROVED: Yes; FPLIST: RC0402_25,RC0402_HD,0402_CC; HEIGHT: 0.40 MM; MFG_NAME01: YAGEO AMERICA; MFG_PN01: RC0402FR-07422RL; ROHS: Yes; Tolerance: 1%
R118 = RES: RES MF 1.0K 1/16W 5% 0402; AGILE_PN: 470-75555; CAD_APPROVED: Yes; FPLIST: RC0402_25,RC0402_HD,RC0402_X2,0402_CC; HEIGHT: 0.41mm; MFG_NAME01: VISHAY INTERTECHNOLOGY; MFG_PN01: CRCW04021K00JNED; ROHS: Yes; Tolerance: 5%
R135 R136 R145 = RES: RES MF ZERO OHM 1/16W 5% 0402; AGILE_PN: 470-75394; CAD_APPROVED: Yes; EN: 101-1-00001; FPLIST: RC0402_25,RC0402_HD,RC0402_X2,0402_CC; HEIGHT: 0.45 MM; KEY Number: 101-1-00001@2; MFG_NAME01: YAGEO AMERICA; MFG_PN01: RC0402JR-070RL; Mfg: VISHAY; Mfg Part No: CRCW04020000Z0**; ROHS: Yes; Temperature: -55°C to +155°C; Tolerance: 5%; VOLTAGE: 1/16W
R137-R140 = RES: RES MF 10K 1/16W 5% 0402; AGILE_PN: 470-75557; ASSY_OPT: DNP; CAD_APPROVED: Yes; FPLIST: RC0402_25,RC0402_HD,0402_CC; HEIGHT: 0.4 MM; MFG_NAME01: VISHAY INTERTECHNOLOGY; MFG_PN01: CRCW040210K0JNED; ROHS: Yes; Tolerance: 5%
R141 = RES: RES MF 10K 1/16W 5% 0402; AGILE_PN: 470-75557; CAD_APPROVED: Yes; FPLIST: RC0402_25,RC0402_HD,0402_CC; HEIGHT: 0.4 MM; MFG_NAME01: VISHAY INTERTECHNOLOGY; MFG_PN01: CRCW040210K0JNED; ROHS: Yes; Tolerance: 5%
SH2 SH3 = RES_SHORT-2: ZERO OHM CUT TRACE 0402 PADS; NO PART TO ORDER; AGILE_PN: 470-76449; CAD_APPROVED: Yes; FPLIST: SH0402,SH0402_CC; HEIGHT: 0.1 MM; MFG_NAME01: LAYOUT ELEMENT ONLY; MFG_PN01: LAYOUT ELEMENT ONLY; ROHS: Yes
SW1 = SW_PB_4P: SW SPST MOM PB NO 50MA 32V SMT; AGILE_PN: 510-78172; CAD_APPROVED: Yes; HEIGHT: 1.9 MM; MFG_NAME01: C&K COMPONENTS; ROHS: Yes; SILK: USER_1; Temp Range: -40° C to +85° C; Temp_Range: -40° C to +85° C; VOLTAGE: 32V
SW2 = SW_PB_4P: SW SPST MOM PB NO 50MA 32V SMT; AGILE_PN: 510-78172; CAD_APPROVED: Yes; HEIGHT: 1.9 MM; MFG_NAME01: C&K COMPONENTS; ROHS: Yes; SILK: USER_2; Temp Range: -40° C to +85° C; Temp_Range: -40° C to +85° C; VOLTAGE: 32V
U6 = FXOS8700CQ_QFN_16P: IC ACCELEROMETER AND MAGNETOMETER SENSOR 3-AXIS 2.5V QFN16; AGILE_PN: 312-80418; CAD_APPROVED: Yes; FPLIST: QFN5X3_0P5_3X3,QFN5X3_0P5_3X3_a; HEIGHT: 1.25MM; MFG_NAME01: FREESCALE SEMICONDUCTOR; ROHS: Yes; SILK: ACCEL; VOLTAGE: 2.5V
U30 = NC7SZ14: IC INV SGL 1.65-5.5V TSSOP5; AGILE_PN: 315-81077; CAD_APPROVED: Yes; HEIGHT: 1.1MM; MFG_NAME01: NEXPERIA; MFG_PN01: 74LVC1G04GW,125; ROHS: Yes; VOLTAGE: 1.65-5.5V
U4 U9 = 74AVC4TD245BQ_DHVQFN16: IC DUAL SUPPLY XCVR XLTR 4BIT 0-3.6V DHVQFN16; AGILE_PN: 312-81329; CAD_APPROVED: Yes; HEIGHT: 1MM; MFG_NAME01: NEXPERIA; MFG_PN01: 74AVC4TD245BQ,115; ROHS: Yes
U26 = 74AVC2T45_8P: IC XCVR/XLTR 2BIT 0.8-3.6V VSSOP8; AGILE_PN: 312-81894; CAD_APPROVED: Yes; HEIGHT: 1MM; MFG_NAME01: NEXPERIA; MFG_PN01: 74AVC2T45DC; ROHS: Yes; Temp Range: -40C to 125C; Temp_Range: -40C to 125C; VOLTAGE: 0.8-3.6V
C12 C97 = CAP_NP: CAP CER 10uF 16V 20% X5R 0603; AGILE_PN: 150-80336; CAD_APPROVED: Yes; FPLIST: CC0603_OV,CC0603; HEIGHT: 1MM; MFG_NAME01: MURATA; MFG_PN01: GRM188R61C106MA73D; Package Size: 0603; Package Type: SMD; ROHS: Yes; Tolerance: 20%; VOLTAGE: 16V
C13 C14 = CAP_NP: CAP CER 27PF 50V 5% C0G 0402; AGILE_PN: 150-30109; CAD_APPROVED: Yes; FPLIST: CC0402_25,CC0402_HD,0402_CC; HEIGHT: .55mm; MFG_NAME01: KEMET; MFG_PN01: C0402C270J5GAC; ROHS: Yes; Tolerance: 5%; VOLTAGE: 50V
D5 = DIODE_SCHTKY: DIODE SCH RECT 10V 2A SOD123F; AGILE_PN: 480-78720; CAD_APPROVED: Yes; HEIGHT: 1.2M; MFG_NAME01: NEXPERIA; MFG_PN01: PMEG1020EH,115; ROHS: Yes; VOLTAGE: 10V
D13 = DIODE_ARRAY_5CH: DIODE TVS UNIDIR 3.3VWM 12VC SOT363; AGILE_PN: 480-79841; CAD_APPROVED: Yes; HEIGHT: 1.1MM; MFG_NAME01: NEXPERIA; MFG_PN01: PESD3V3L5UY,115; REQUESTED_COMPLETION_DATE: Not an expedite request; ROHS: Yes; Temp Range: -65°C ~ 150°C; Temp_Range: -65°C ~ 150°C
J2 = CONN_HDR_5X2: HDR 2X5 SMT 50MIL CTR 246H AU; AGILE_PN: 211-79478; CAD_APPROVED: Yes; HEIGHT: 6.25MM; MFG_NAME01: SAMTEC; ROHS: Yes; SILK: RT685 SWD
R13 R30 R31 R33 = RES: RES MF 12.1K 1/16W 1% 0402; AGILE_PN: 470-76098; CAD_APPROVED: Yes; FPLIST: RC0402_25,RC0402_HD,0402_CC; HEIGHT: 0.4 MM; MFG_NAME01: BOURNS; MFG_PN01: CR0402-FX-1212GLF; ROHS: Yes; Tolerance: 1%
R14 = RES: RES MF ZERO OHM 1/16W 5% 0402; AGILE_PN: 470-75394; CAD_APPROVED: Yes; FPLIST: RC0402_25,RC0402_HD,RC0402_X2,0402_CC; HEIGHT: 0.45 MM; MFG_NAME01: YAGEO AMERICA; MFG_PN01: RC0402JR-070RL; ROHS: Yes; Tolerance: 5%; VOLTAGE: 1/16W
R28 = RES: RES MF 1.5K 1/16W 5% 0402; AGILE_PN: 470-76303; CAD_APPROVED: Yes; FPLIST: RC0402_25,RC0402_HD,0402_CC; HEIGHT: 0.40 MM; MFG_NAME01: VISHAY INTERTECHNOLOGY; MFG_PN01: CRCW04021K50JNED; ROHS: Yes; Tolerance: 5%; VOLTAGE: 1/16W
R125 = RES: RES MF ZERO OHM 1/16W 5% 0402; AGILE_PN: 470-75394; ASSY_OPT: DNP; CAD_APPROVED: Yes; EN: 101-1-00001; FPLIST: RC0402_25,RC0402_HD,RC0402_X2,0402_CC; HEIGHT: 0.45 MM; KEY Number: 101-1-00001@2; MFG_NAME01: YAGEO AMERICA; MFG_PN01: RC0402JR-070RL; Mfg: VISHAY; Mfg Part No: CRCW04020000Z0**; ROHS: Yes; Temperature: -55°C to +155°C; Tolerance: 5%; VOLTAGE: 1/16W
U1 = LPC432_BGA_100P: IC MCU  CORTEX M4 CORE 512kB FLASH 2.4-3.6V BGA100; AGILE_PN: 344-02176; CAD_APPROVED: Yes; HEIGHT: 1.2MM; MFG_NAME01: NXP SEMICONDUCTORS; MFG_PN01: LPC4322JET100E; ROHS: Yes; VOLTAGE: 2.4-3.6V
U2 U5 U10 = 74LVCH1T45_6P: IC XCVR XLATING DUAL 3-STATE 1.2- 5.5V TSSOP6; AGILE_PN: 312-81277; CAD_APPROVED: Yes; HEIGHT: 1.1MM; MFG_NAME01: NEXPERIA; ROHS: Yes; VOLTAGE: 1.2- 5.5V
U3 = 74AVC2T45_8P: IC XCVR 0.8-3.6V/0.8-3.6V TSSOP8; AGILE_PN: 312-80487; CAD_APPROVED: Yes; HEIGHT: 1.1 MM; MFG_NAME01: NEXPERIA; MFG_PN01: 74AVC2T45DP,125; ROHS: Yes; VOLTAGE: 0.8-3.6V
U7 = NX3DV2567GU_XQFN_16P: IC LIN SW 4PDT 1.4-4.3V XQFN16; AGILE_PN: 315-80822; CAD_APPROVED: Yes; HEIGHT: 0.5 MM; MFG_NAME01: NXP SEMICONDUCTORS; MFG_PN01: NX3DV2567GU,115; ROHS: Yes; VOLTAGE: 1.4-4.3V
Y1 = XTAL: XTAL 12MHZ RSN -- 18PF 30PPM SMT; AGILE_PN: 230-78082; CAD_APPROVED: Yes; HEIGHT: 3.3MM; MFG_NAME01: ABRACON CORP; MFG_PN01: ABLS2-12.000MHZ-D4Y-T; ROHS: Yes

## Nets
3v3_LINK_CORE: C91.1 C93.1 C96.1 L13.1 U1.E4(VDDREG1) U1.E5(VDDREG2) U1.F4(VDDREG3)
+2.5V_LINK: C23.1 C38.1 C92.1 C94.1 C95.1 C97.1 C98.1 C99.1 C100.1 C140.1 JP4.1 L13.2 R6.1 R24.2 R29.1 R30.2 R31.2 R32.1 R33.1 R37.1 R126.1 R127.1 TP1.1(TP) U1.B2(VDDA) U1.C5(VBAT) U1.D1(USB0_VDDA3V3_DRIVER) U1.D2(USB0_VDDA3V3) U1.F10(VDDIO1) U1.K5(VDDIO2) U2.1(VCCA) U3.1(VCCA) U4.1(VCCA) U5.1(VCCA) U9.1(VCCA) U9.2(DIR1) U9.7(DIR4) U9.15(DIR2) U10.1(VCCA) U26.1(VCCA) ; also on sheet 7
AVDD: C35.1 L3.2 U8.23(AVDD)
GND: C2.2 C3.2 C4.2 C5.2 C8.2 C10.1 C11.2 C12.2 C13.2 C14.1 C16.1 C18.2 C19.2 C21.2 C22.1 C23.2 C24.2 C25.1 C26.2 C27.2 C28.2 C29.2 C30.2 C31.2 C32.2 C33.2 C34.2 C35.2 C36.1 C37.1 C38.2 C91.2 C92.2 C93.2 C94.2 C95.2 C96.2 C97.2 C98.2 C99.2 C100.2 C139.1 C140.2 C143.2 C322.2 C329.2 C330.2 C332.2 C333.2 D2.C(CATHODE) D3.3(Double_Cathode) D4.3(Double_Cathode) D13.2(A) D14.3(Double_Cathode) J2.3(A2) J2.5(A3) J3.1 J4.1 J18.4 JP1.2 JP3.2 JS1.1 Q3.1(SOURCE1) Q3.3(DRAIN2) Q3.4(SOURCE2) Q3.5(GATE2) Q3.8(DRAIN2) Q4.1(SOURCE1) Q4.4(SOURCE2) R4.2 R5.2 R8.2 R9.2 R12.2 R13.2 R15.2 R17.2 R19.2 R20.2 R21.2 R23.2 R25.2 R27.2 R38.2 R47.2 R135.2 R136.2 R141.2 SW1.3 SW1.4 SW2.3 SW2.4 TP2.1(TP) U1.C2(VSSA) U1.C8(VSS1) U1.D3(USB0_VSSA_TERM) U1.D4(VSS2) U1.D5(VSS3) U1.F2(USB0_VSSA_REF) U1.G8(VSS4) U1.J3(VSS5) U1.J6(VSS6) U2.2(GND) U3.4(GND) U4.8(GND1) U4.17(NC/GND2) U5.2(GND) U5.5(DIR) U6.3(RSVD1) U6.5(GND1) U6.12(GND2) U6.13(RSVD2) U7.1(1Y0) U7.5(2Y0) U7.6(GND) U7.9(3Y0) U7.15(1Y1) U8.5(DGND) U8.9(CPGND) U8.14(HPOUTFB) U8.17(LINEOUTFB) U8.22(AGND) U8.33(PGND) U9.8(GND1) U9.10(DIR3) U9.17(NC/GND2) U10.2(GND) U26.4(GND) U26.5(DIR) U30.3(GND) U35.2(GND) U36.2(GND) ; also on sheet 1 2 3 4 5 7 8 9 14
P1V8_CODEC: C21.1 C27.1 C30.1 JS2.1 L3.1 U8.6(DCVDD) U8.7(CPVDD) ; also on sheet 1
VDD_ACCEL: C28.1 C29.1 JP15.2 U6.14(VDD)
VDD_CODEC: C33.1 C329.1 C333.1 JS3.1 L2.1 R411.1 R412.1 U8.4(DBVDD) U35.3(VCCA) U35.6(OE) U36.3(VCCA) U36.6(OE)
VDD_LDO_3V3: JP15.1 ; also on sheet 2 7 14
VDD_LINK: C10.2 C12.1 C16.2 C25.2 C36.2 J2.1(A1) JP2.2 R16.1 R41.1 R43.1 U2.6(VCCB) U3.8(VCCB) U5.6(VCCB) U10.6(VCCB)
VDD_TARGET: JS13.2 ; also on sheet 4 7
VDDIO1: C322.1 C330.1 C332.1 D5.A JP2.1 R10.1 R39.2 R116.1 R117.1 R137.1 R138.1 R139.1 R140.1 R145.1 R409.1 R410.1 U7.14(VCC) U30.5(VCC) U35.7(VCCB) U36.7(VCCB) ; also on sheet 2 4 5 7 8 14
ACC_INT1: R40.1 R138.2 U6.11(INT1)
ACC_INT2: R137.2 TP37.1(TP) U6.9(INT2)
ACCEL_RST_8700: R141.1 R144.2 U6.16(RST)
ALT_INT_AMP: JP6.3 ; also on sheet 5
ALT_INT_CODEC: R48.1 R401.2
BOOT0_LED: R6.2 R7.1 U1.K2(P1_1/GPIO0[8]/CTOUT_7/EMC_A6/SGPIO8/SSP0_MISO/EMC_D13)
BOOT1: R9.1 U1.K1(P1_2/GPIO0[9]/CTOUT_6/EMC_A7/SGPIO9/SSP0_MOSI/EMC_D14)
BOOT2: R29.2 U1.C6(P2_8/SGPIO15/CTOUT_0/U3_DIR/EMC_A8/GPIO5[7])
BOOT3: R21.1 U1.B10(P2_9/GPIO1[10]/CTOUT_3/U3_BAUD/EMC_A0)
BRDG_INTR-ISP_DIR: R25.1 U1.J7(P1_11/GPIO1[4]/U1_CTS/CTOUT_15/EMC_D4/SD_DAT2) U4.10(DIR3)
BRIDGE_INTR-ISP: R36.1 ; also on sheet 14
BRIDGE_L_INTR-ISP: R34.2 U1.J5(P1_9/GPIO1[2]/U1_RTS/CTOUT_11/EMC_D2/SD_DAT0)
BRIDGE_L_MISO: U1.J1(P1_3/GPIO0[10]/CTOUT_8/SGPIO10/~{EMC_OE}/USB0_IND1/SSP1_MISO/SD_RST) U26.2(1A)
BRIDGE_L_MOSI: U1.J2(P1_4/GPIO0[11]/CTOUT_9/SGPIO11/~{EMC_BLS0}/USB0_IND0/SSP1_MOSI/EMC_D15/SD_VOLT1) U4.6(A4)
BRIDGE_L_SCK: U1.K9(P1_19/ENET_TX_CLK/ENET_REF_CLK/SSP1_SCK/CLKOUT/I2S0_RX_MCLK/I2S1_TX_SCK) U4.4(A2)
BRIDGE_L_SSEL: U1.K10(P1_20/GPIO0[15]/SSP1_SSEL/ENET_TXD1/T0_CAP2/SGPIO13/EMC_D11) U4.3(A1)
BRIDGE_UART_RXD: U1.G10(P2_0/SGPIO4/U0_TXD/EMC_A13/USB0_PPWR/GPIO5[0]/T3_CAP0/ENET_MDC) U9.4(A2)
BRIDGE_UART_TXD: U1.G7(P2_1/SGPIO5/U0_RXD/EMC_A12/USB0_PWR_FAULT/GPIO5[1]/T3_CAP1) U9.5(A3)
BYP_8700: C31.1 U6.2(BYP)
CPCA: C20.1 U8.8(CPCA)
CPCB: C20.2 U8.10(CPCB)
CRST_8700: C143.1 U6.8(CRST)
ELECTRET_MIC: D14.1(CATHODE1) P1.2(GND) R42.1 R49.3
HP_OUTL: C11.1 C15.1 D3.1(CATHODE1) J4.2 U8.13(HPOUTL)
HP_OUTR: C2.1 C17.1 D3.2(CATHODE2) J4.3 U8.15(HPOUTR)
I2C_SA0_8700: R135.1 R139.2 U6.7(SA0/MISO)
I2C_SA1_8700: R136.1 R140.2 U6.10(SA1/~{CS})
I2PIO2_0-SD0_D(0)_SCL: JS6.1 R126.2 U1.D6(I2C0_SCL)
I2PIO2_0-SD0_D(0)_SDA: JS5.1 R127.2 U1.E6(I2C0_SDA)
I2S_BCLK_CODEC: R400.2 U8.29(BCLK/GPIO4) ; also on sheet 3
I2S_DAI_CODEC: R404.2 U8.31(ADCDAT) ; also on sheet 3
I2S_DAO_AMP: JP7.3 ; also on sheet 5
I2S_DAO_CODEC: R402.2 U8.32(DACDAT) U35.4(A2) ; also on sheet 3
I2S_WS_CODEC: R399.2 U8.30(LRCLK) ; also on sheet 3
IF_DETECT: J2.9(A5) JS1.2 R28.1
IF_JTAG_TDI: D13.1(K1) J2.8(B4) R26.2
IF_RST: D13.3(K2) J2.10(B5) JP17.1 ; also on sheet 4
IF_TCK_SWCLK: D13.6(K5) J2.4(B2) JP18.1 U7.3(2Y1) ; also on sheet 4
IF_TDO_SWO: D13.4(K3) J2.6(B3) R41.2 U5.4(B) U7.11(4Y1) ; also on sheet 4
JTAG_RESET: U1.D10(P2_5/SGPIO14/CTIN_2/USB1_VBUS/ADCTRIG1/GPIO5[5]/T3_MAT2/USB0_IND0) U10.3(A)
JTAG_RESET_TXEN: R47.1 U1.G9(P2_6/SGPIO7/U0_DIR/EMC_A10/USB0_IND0/GPIO5[6]/CTIN_7/T3_CAP3/~{EMC_BLS1}) U10.5(DIR)
JTAG_TDI: U1.J10(P1_18/GPIO0[13]/U2_DIR/ENET_TXD0/T0_MAT3/CAN1_RD/SGPIO12/EMC_D10) U3.3(2A)
LED_BLUE: D8.C(CATHODE) Q3.6(DRAIN1) Q3.7(DRAIN1)
LED_GREEN: D10.C(CATHODE) Q4.3(DRAIN2) Q4.8(DRAIN2)
LED_RED: D9.C(CATHODE) Q4.6(DRAIN1) Q4.7(DRAIN1)
LININL: C7.1 U8.26(IN2L)
LININL_JACK: C7.2 C8.1 D4.1(CATHODE1) D14.2(CATHODE2) J3.2 P1.1(Out) R19.1
LININR: R49.2 U8.24(IN2R)
LININR_JACK: C4.1 C6.2 D4.2(CATHODE2) J3.3 R4.1
LINK2_ISP_BOOT: JP1.1 U1.C10(P2_7/GPIO0[7]/CTOUT_1/U3_UCLK/EMC_A9/T3_MAT3)
MCLK_CODEC: R403.2 U8.28(MCLK) U35.5(A1)
MICBIAS: C32.1 R42.2 U8.20(MICBIAS)
MICVDD: C26.1 L2.2 U8.19(MICVDD)
nRESET_TRGT: R125.1 U30.2(A) ; also on sheet 4 5 7 14
nTRST_LINK2: R33.2 TP3.1(TP) U1.B4(~{TRST})
P0_0: JP6.2 ; also on sheet 8
P0_0_CODEC_ALT_IN: JP6.1 R401.1
P0_1_FC0_TX: U9.12(B3) ; also on sheet 8 14
P0_2_FC0_RX_LINK: R46.2 ; also on sheet 14
P0_7_I2S_CLK: R400.1 TP10.1(TP) ; also on sheet 5 8
P0_8_I2S_WS: R399.1 TP9.1(TP) ; also on sheet 5 8
P0_9_CODEC_DAI: JP8.1 R404.1
P0_9_I2S_DAI: JP8.3 ; also on sheet 5
P0_9_I2S_DATA: JP8.2 ; also on sheet 8 14
P0_10: C5.1 R11.2 SW2.1 SW2.2 ; also on sheet 8
P0_14: Q4.5(GATE2) ; also on sheet 8
P0_15_FC2_SCL: JS6.2 ; also on sheet 8 14
P0_16_FC2_SDA: JS5.2 ; also on sheet 8 14
P0_17_FC2_SDA: SH2.2 ; also on sheet 8 14
P0_18_FC2_SCL: SH3.2 ; also on sheet 8 14
P0_23_CODEC_DAO: JP7.1 R402.1 U35.1(B2)
P0_23_I2S_DATA_TX: JP7.2 ; also on sheet 4 8
P0_26: Q3.2(GATE1) ; also on sheet 8
P0_31: Q4.2(GATE1) ; also on sheet 8
P1_1: C3.1 R10.2 SW1.1 SW1.2 ; also on sheet 8
P1_5_SPI_MOSI: JP30.1 ; also on sheet 3 8 14
P1_7_RST: R144.3 ; also on sheet 4
P1_10_MCLK: R403.1 TP8.1(TP) U35.8(B1) ; also on sheet 8 14
P1_11_SPI_CLK_A: U4.13(B2) ; also on sheet 9 14
P1_12_SPI_MISO_A: U26.7(1B) ; also on sheet 9 14
P1_13_SPI_MOSI_A: U4.11(B4) ; also on sheet 9 14
P1_14_SPI_SS0_A: U4.14(B1) ; also on sheet 9 14
P2_24_SWO: U7.12(4Z) ; also on sheet 8
P2_25_SWD_CLK: U7.4(2Z) ; also on sheet 8
P2_26_SWDIO: D13.5(K4) J2.2(B1) JP19.1 ; also on sheet 4 8
P2_29_I3C0_SCL: J18.1 R406.1 R409.2 TP7.1(TP) U36.1(B2) ; also on sheet 3 5 8
P2_30_I3C0_SDA: J18.2 R118.1 R405.1 R410.2 TP6.1(TP) U36.8(B1) ; also on sheet 5 8
P2_31_I3C0_PUR: J18.3 R118.2 ; also on sheet 8
RESET_FXO: R144.1 U30.4(Y)
SCL_CODEC: R406.2 R411.2 U8.2(SCLK) U36.4(A2)
SDA_CODEC: R45.1 R405.2 R412.2 U36.5(A1)
SW2_OUT: C22.2 C37.2 C139.2 JS2.2 JS3.2 R11.1 U4.16(VCCB) U9.16(VCCB) U26.8(VCCB) ; also on sheet 1 3 4 5 7 8 9 14
SWDCLK_LINK2: R8.1 TP5.1(TP) U1.H2(TCK/SWDCLK)
SWDIO_LINK2: TP4.1(TP) U1.C4(TMS/SWDIO)
TCK_SWCLK: U1.H10(P1_17/GPIO0[12]/U2_UCLK/ENET_MDIO/T0_CAP3/CAN1_TD/SGPIO11) U3.2(1A)
TDO_SWO: U1.J8(P1_14/GPIO1[7]/U1_RXD/EMC_D7/T0_MAT2/SGPIO10) U5.3(A)
TMS_SWDIO: U1.K4(P1_6/GPIO1[9]/CTIN_5/~{EMC_WE}/~{EMC_BLS0}/SGPIO14/SD_CMD) U2.3(A)
TMS_SWDIO_TXEN: R20.1 U1.J4(P1_5/GPIO1[8]/CTOUT_10/~{EMC_CS0}/USB0_PWR_FAULT/SSP1_SSEL/SGPIO15/SD_POW) U2.5(DIR)
USB_DM_LINK: U1.E2(USB0_DM) ; also on sheet 2
USB_DP_LINK: U1.E1(USB0_DP) ; also on sheet 2
USB_ID: R14.2 U1.F1(USB0_ID)
USB_ID_LINK: R14.1 ; also on sheet 2
USB_VBUS_LINK: U1.E3(USB0_VBUS) ; also on sheet 2
V_LED: JS13.1 R92.1 R96.1 R97.1
VMIDC: C34.1 U8.21(VMIDC)
N16965957: C19.1 U8.11(CPVOUTP)
N16965996: C18.1 U8.12(CPVOUTN)
N17023483: D9.A(ANODE) R96.2
N17023485: D8.A(ANODE) R92.2
N17023487: D10.A(ANODE) R97.2
N17103807: R46.1 U9.13(B2)
N17103888: JP4.2 R23.1 U4.9(~{OE}) U9.9(~{OE})
N17103964: R37.2 U4.2(DIR1) U4.7(DIR4) U4.15(DIR2)
N17104052: R34.1 U4.5(A3)
N17104054: R36.2 U4.12(B3)
N17136364: R13.1 U1.F3(USB0_RREF)
N17136422: C13.1 U1.B1(XTAL1) Y1.2
N17136435: R31.1 U1.A6(DBGEN)
N17136473: R32.2 U1.A4(WAKEUP0)
N17136502: R30.1 U1.B6(~{RESET})
N17136518: C14.2 U1.C1(XTAL2) Y1.1
N17202709: R125.2 U7.8(3Z)
N17202739: JP3.1 R39.1 U7.2(S)
N17208284: R28.2 U1.A10(P2_13/GPIO1[13]/CTIN_4/EMC_A4/U2_DIR)
N17208314: R5.1 U1.J9(P6_2/GPIO3[1]/EMC_CKEOUT1/U0_DIR/I2S0_RX_SDA/T2_CAP1)
N17208318: R15.1 U1.F9(P6_5/GPIO3[4]/CTOUT_6/U0_RXD/~{EMC_RAS})
N17208322: R12.1 U1.F8(P6_9/GPIO3[5]/~{EMC_DYCS0}/T2_MAT2)
N17208326: R17.1 U1.C9(P6_11/GPIO3[7]/EMC_CKEOUT0/T2_MAT3)
N17337786: R35.1 U3.7(1B)
N17337788: JP18.2 R35.2
N17337803: R26.1 U3.6(2B)
N17337821: R24.1 U3.5(DIR)
N17337994: R16.2 R18.1 U2.4(B)
N17338012: JP19.2 R18.2
N17338109: R43.2 R44.1 U10.4(B)
N17338127: JP17.2 R44.2
N17340148: D5.C JP2.3
N17344064: D2.A(ANODE) R7.2
N17792148: R45.2 U8.3(SDA)
N17792155: R48.2 U8.1(IRQ/GPIO1)
N17851401: C6.1 R49.1
N18526070: C24.1 R145.2 U6.1(VDDIO)
N18526135: R117.2 SH3.1 U6.4(SCL/SCLK)
N18526137: R116.2 SH2.1 U6.6(SDA/MOSI)
N18526318: JP30.2 R40.2
N21332853: C15.2 R27.1
N21332854: C17.2 R38.1

Not connected (* = marked no-connect by the designer): J2 7(A4)*; J3 4*; J4 4*; U1 A1(ADC0_1/ADC1_1)* A2(ADC0_0/ADC1_0/DAC)* A3(ADC0_3/ADC1_3)* A5(RTCX1)* A7(P3_3/SPI_SCK/SSP0_SCK/SPIFI_SCK/CGU_OUT1/I2S0_TX_MCLK/I2S1_TX_SCK)* A8(P3_0/I2S0_RX_SCK/I2S0_RX_MCLK/I2S0_TX_SCK/I2S0_TX_MCLK/SSP0_SCK)* A9(P2_11/GPIO1[11]/CTOUT_5/U2_RXD/EMC_A2)* B3(ADC0_2/ADC1_2)* B5(RTCX2)* B7(P3_5/GPIO1[15]/SPIFI_SIO2/U1_RXD/I2S0_TX_SDA/I2S1_RX_WS/LCD_VD12)* B8(P3_4/GPIO1[14]/SPIFI_SIO3/U1_TXD/I2S0_TX_WS/I2S1_RX_SDA/LCD_VD13)* B9(P2_12/GPIO1[12]/CTOUT_4/EMC_A3/U2_UCLK)* C3(RTC_ALARM)* C7(P3_6/GPIO0[6]/SPI_MISO/SSP0_SSEL/SPIFI_MISO/SSP0_MISO)* D7(P3_7/SPI_MOSI/SSP0_MISO/SPIFI_MOSI/GPIO5[10]/SSP0_MOSI)* D8(P2_3/SGPIO12/I2C1_SDA/U3_TXD/CTIN_1/GPIO5[3]/T3_MAT0/USB0_PPWR)* D9(P2_4/SGPIO13/I2C1_SCL/U3_RXD/CTIN_0/GPIO5[4]/T3_MAT1/USB0_PWR_FAULT)* E7(P3_8/SPI_SSEL/SSP0_MOSI/SPIFI_CS/GPIO5[11]/SSP0_SSEL)* E8(P2_10/GPIO0[14]/CTOUT_2/U2_TXD/EMC_A1)* E9(USB1_DP)* E10(USB1_DM)* F5(P2_2/SGPIO6/U0_UCLK/EMC_A11/USB0_IND1/GPIO5[2]/CTIN_6/T3_CAP2/~{EMC_CS1})* F6(P6_4/GPIO3[3]/CTIN_6/U0_TXD/~{EMC_CAS})* F7(P3_1/I2S0_TX_WS/I2S0_RX_WS/CAN0_RD/USB1_IND1/GPIO5[8]/LCD_VD15)* G1(P0_1/GPIO0[1]/SSP1_MOSI/ENET_COL/SGPIO1/ENET_TX_EN/I2S1_TX_SDA)* G2(P0_0/GPIO0[0]/SSP1_MISO/ENET_RXD1/SGPIO0/I2S0_TX_WS/I2S1_TX_WS)* G3(TDI)* G4(P1_7/GPIO1[0]/U1_DSR/CTOUT_13/EMC_D0/USB0_PPWR)* G5(P6_1/GPIO3[0]/~{EMC_DYCS1}/U0_UCLK/I2S0_RX_WS/T2_CAP0)* G6(P3_2/I2S0_TX_SDA/I2S0_RX_SDA/CAN0_TD/USB1_IND0/GPIO5[9]/LCD_VD14)* H1(P1_0/GPIO0[4]/CTIN_3/EMC_A5/SSP0_SSEL/SGPIO7/EMC_D12)* H3(TDO/SWO)* H4(PF_4/SSP1_SCK/GP_CLKIN/TRACECLK/I2S0_TX_MCLK/I2S0_RX_SCK)* H5(P1_8/GPIO1[1]/U1_DTR/CTOUT_12/EMC_D1/SD_VOLT0)* H6(P1_10/GPIO1[3]/U1_RI/CTOUT_14/EMC_D3/SD_DAT1)* H7(P6_0/I2S0_RX_MCLK/I2S0_RX_SCK)* H8(P1_13/GPIO1[6]/U1_TXD/EMC_D6/T0_CAP0/SGPIO9/SD_CD)* H9(P1_16/GPIO0[3]/U2_RXD/SGPIO3/ENET_CRS/T0_MAT0/EMC_D9/ENET_RX_DV)* K3(CLK0/EMC_CLK0/CLKOUT/SD_CLK/EMC_CLK01/SSP1_SCK/ENET_TX_CLK/ENET_REF_CLK)* K6(CLK2/EMC_CLK3/CLKOUT/SD_CLK/EMC_CLK23/I2S0_TX_MCLK/I2S1_RX_SCK)* K7(P1_12/GPIO1[5]/U1_DCD/EMC_D5/T0_CAP1/SGPIO8/SD_DAT3)* K8(P1_15/GPIO0[2]/U2_TXD/SGPIO2/ENET_RXD0/T0_MAT1/EMC_D8)*; U6 15(NC)*; U7 7(3Y1)* 10(NC)* 13(4Y0)* 16(1Z)*; U8 16(LINEOUTL)* 18(LINEOUTR)* 25(IN1R/DMICDAT2)* 27(IN1L/DMICDAT1)*; U9 3(A1)* 6(A4)* 11(B4)* 14(B1)*; U26 3(2A)* 6(2B)*; U30 1(NC)*

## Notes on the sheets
sheet 10
- ACC sensor
- I2C Address 0X1E
- LEDS
- RED LED
- USER BUTTONS
- I3C
sheet 11
- Link2 Level Translators
- Target MIMXRT6xx
- Link2 side
- Short JP4 when using
  Pmod SPI interface or
  FC0 UART at J16 (FTDI)
- BRDG_INTR-ISP_DIR:
  DIR3 = 0 Link2 < MIMXRT6xx
  DIR3 = 1 Link2 > MIMXRT6xx
sheet 12
- NC
- TARGET_UART_CTRL
- NC
- ISP_CTRL
- NC
- SSP0_SCK_LINK
- NC
- NC
- TRACE_D0
- TRACE_D1
- NC
- SSP0_MISO_LINK
- NC
- CUR_MEAS_SEL
- NC
- SSP0_MOSI_LINK
- NC
- SSP0_SSEL_LINK
- NC
- TRACE_CLK
- NC
- TRACE_D2
- NC
- TRACE_D3
- LINK2 BOOT MODE
- Link2
  LPC4322 Boot Mode
  DFU USB0 = B3:0 = 0101
- default
  shunt open
- 10-pin SWD
- RED LED
- Short JP1 to force DFU boot mode
  to re-program LPC4322 internal flash
- Target
  MIMXRT6xx
  SWD Debug
- default open
- Link2 probe connected to:      JP3
- Buffer Power Select:         JP2
- On-board Target
  Off-board Target
- Open (default)
  Shorted
- On-board Target
  Off-board Target
- 1 - 2 (default)
  2 - 3
sheet 13
- AUDIO CODEC
- ELECTRET MIC
- Audio Line In
- GND pour in audio analog
  area tied to HPOUTFB pin.
- GND pour in audio analog
  area tied to HPOUTFB pin.
- Codec I2C addrs = 0b0011010
- Line out / headphone out
